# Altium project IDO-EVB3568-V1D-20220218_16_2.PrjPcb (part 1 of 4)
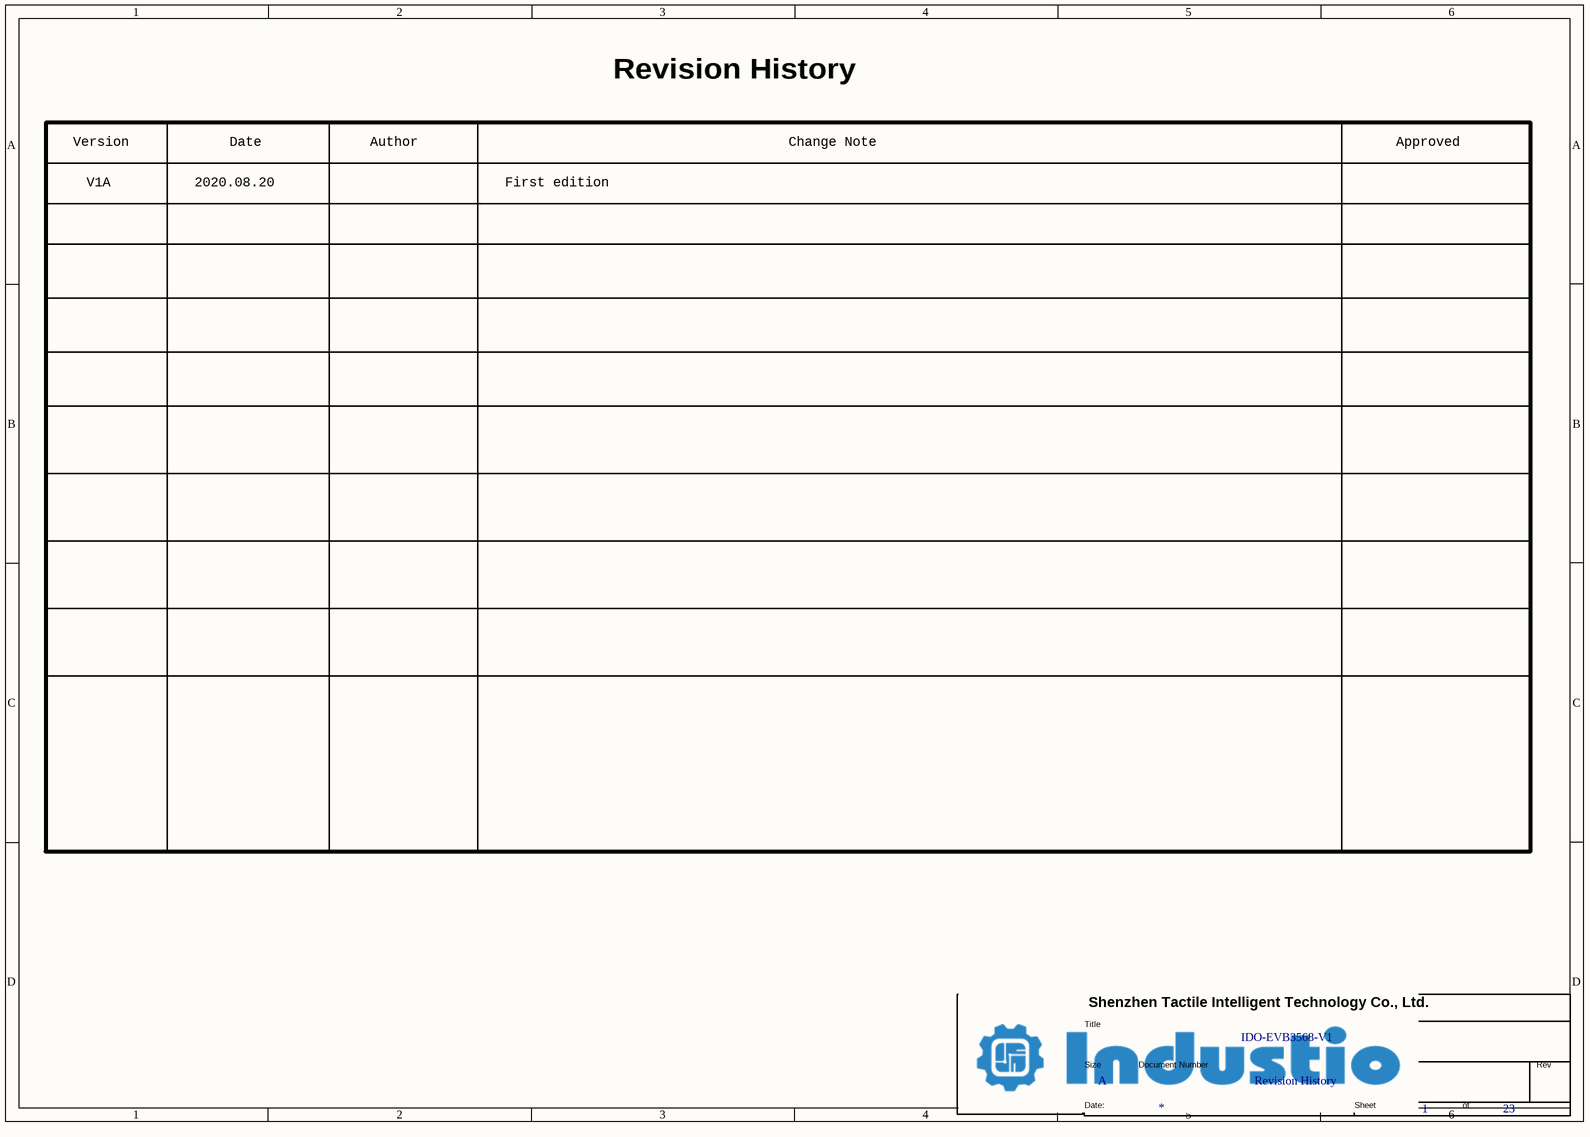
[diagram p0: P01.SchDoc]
23 sheets, 977 parts. Net scope: global (net labels, ports and power ports of the same name join across sheets).
Sheets:
  P01.SchDoc
  P02.SchDoc
  P03.SchDoc
  P04.SchDoc
  P05.SchDoc
  P06.SchDoc
  P07.SchDoc
  P08.SchDoc
  P09.SchDoc
  P10.SchDoc
  P11.SchDoc
  P12.SchDoc
  P13.SchDoc
  P14.SchDoc
  P15.SchDoc
  P16.SchDoc
  P17.SchDoc
  P18.SchDoc
  P19.SchDoc
  P20.SchDoc
  P21.SchDoc
  P22.SchDoc
  P23.SchDoc

## Sheet P01.SchDoc
size 297 x 209 mm

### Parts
(Parts that share a designator on the sheet are numbered #1, #2 ... from top to bottom, then left to right.)
*#1  Doc: Revision History  Title: IDO-EVB3568-V1  Page Size: A  Page Number: 1  Page Count: 23  (hidden comment: TitleBlock1)  (graphical)

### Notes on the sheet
- Revision History
- Version
- V1A
- 2020.08.20
- Date
- Author
- First edition
- Change Note
- Approved

## Sheet P02.SchDoc
size 594 x 420 mm
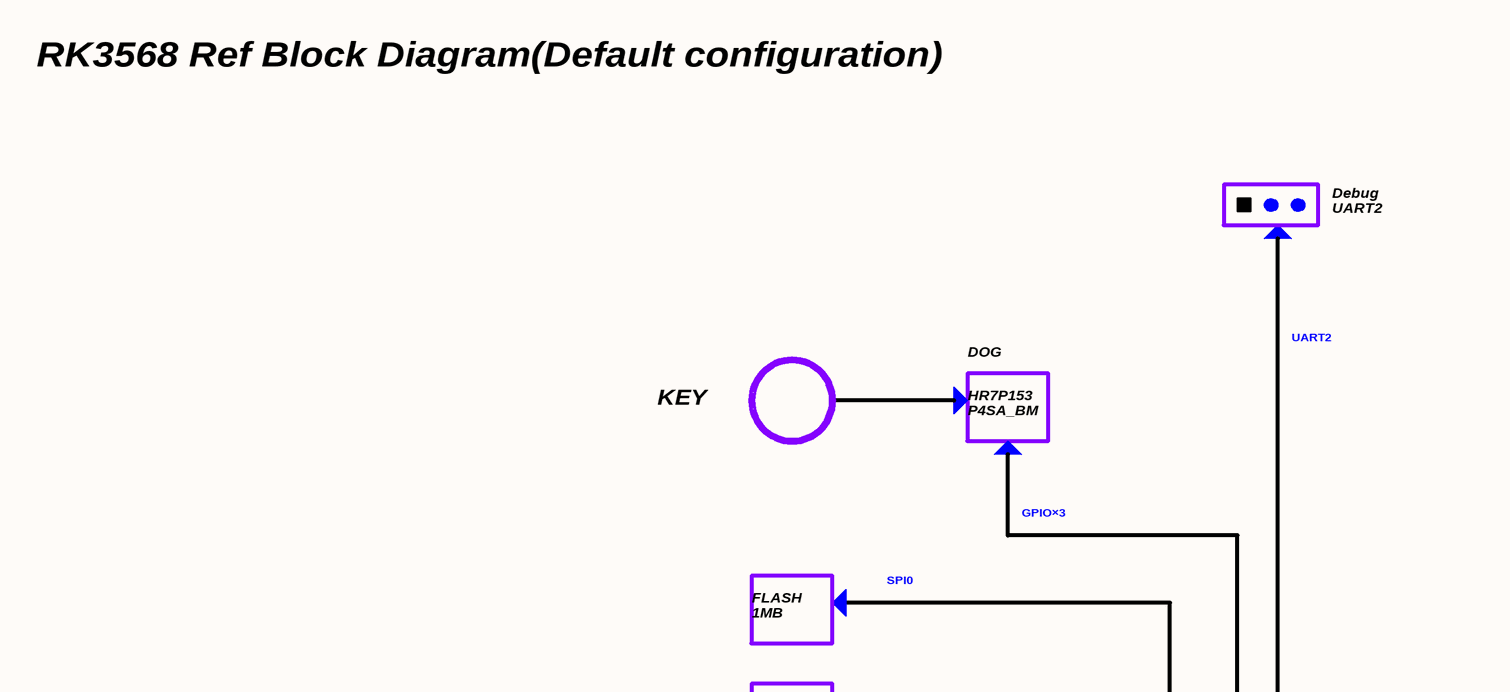
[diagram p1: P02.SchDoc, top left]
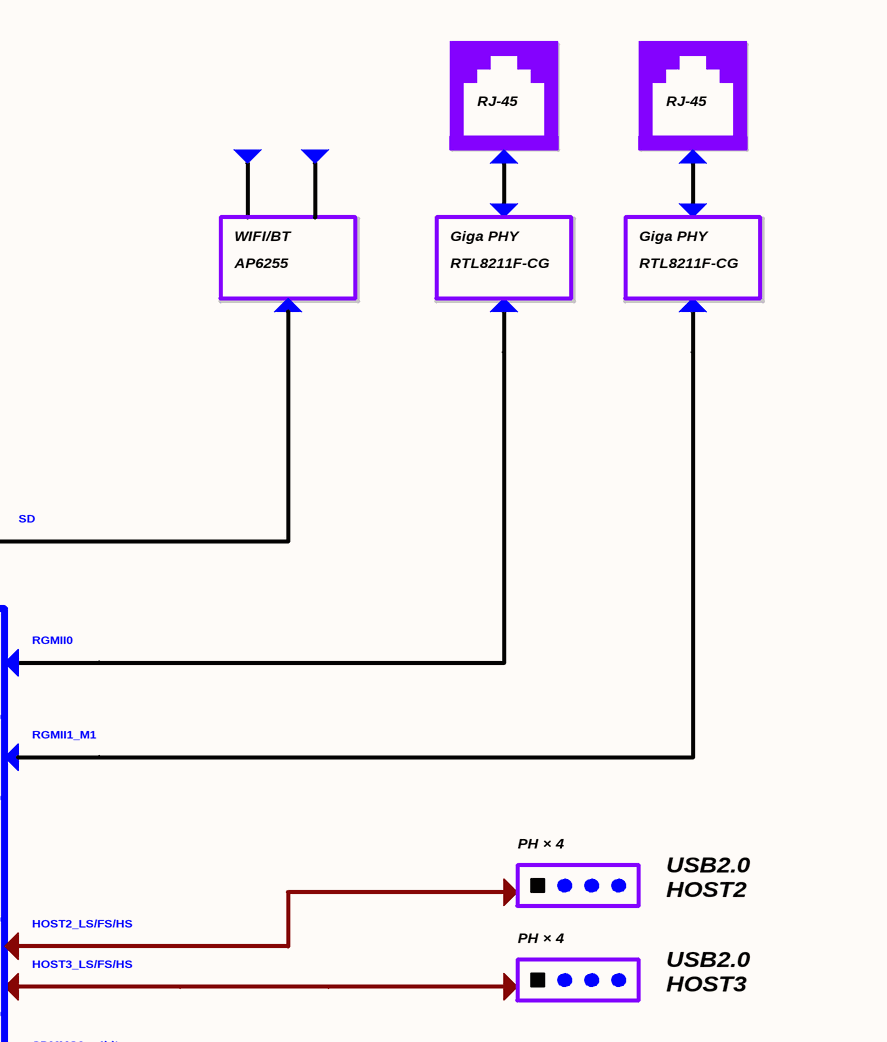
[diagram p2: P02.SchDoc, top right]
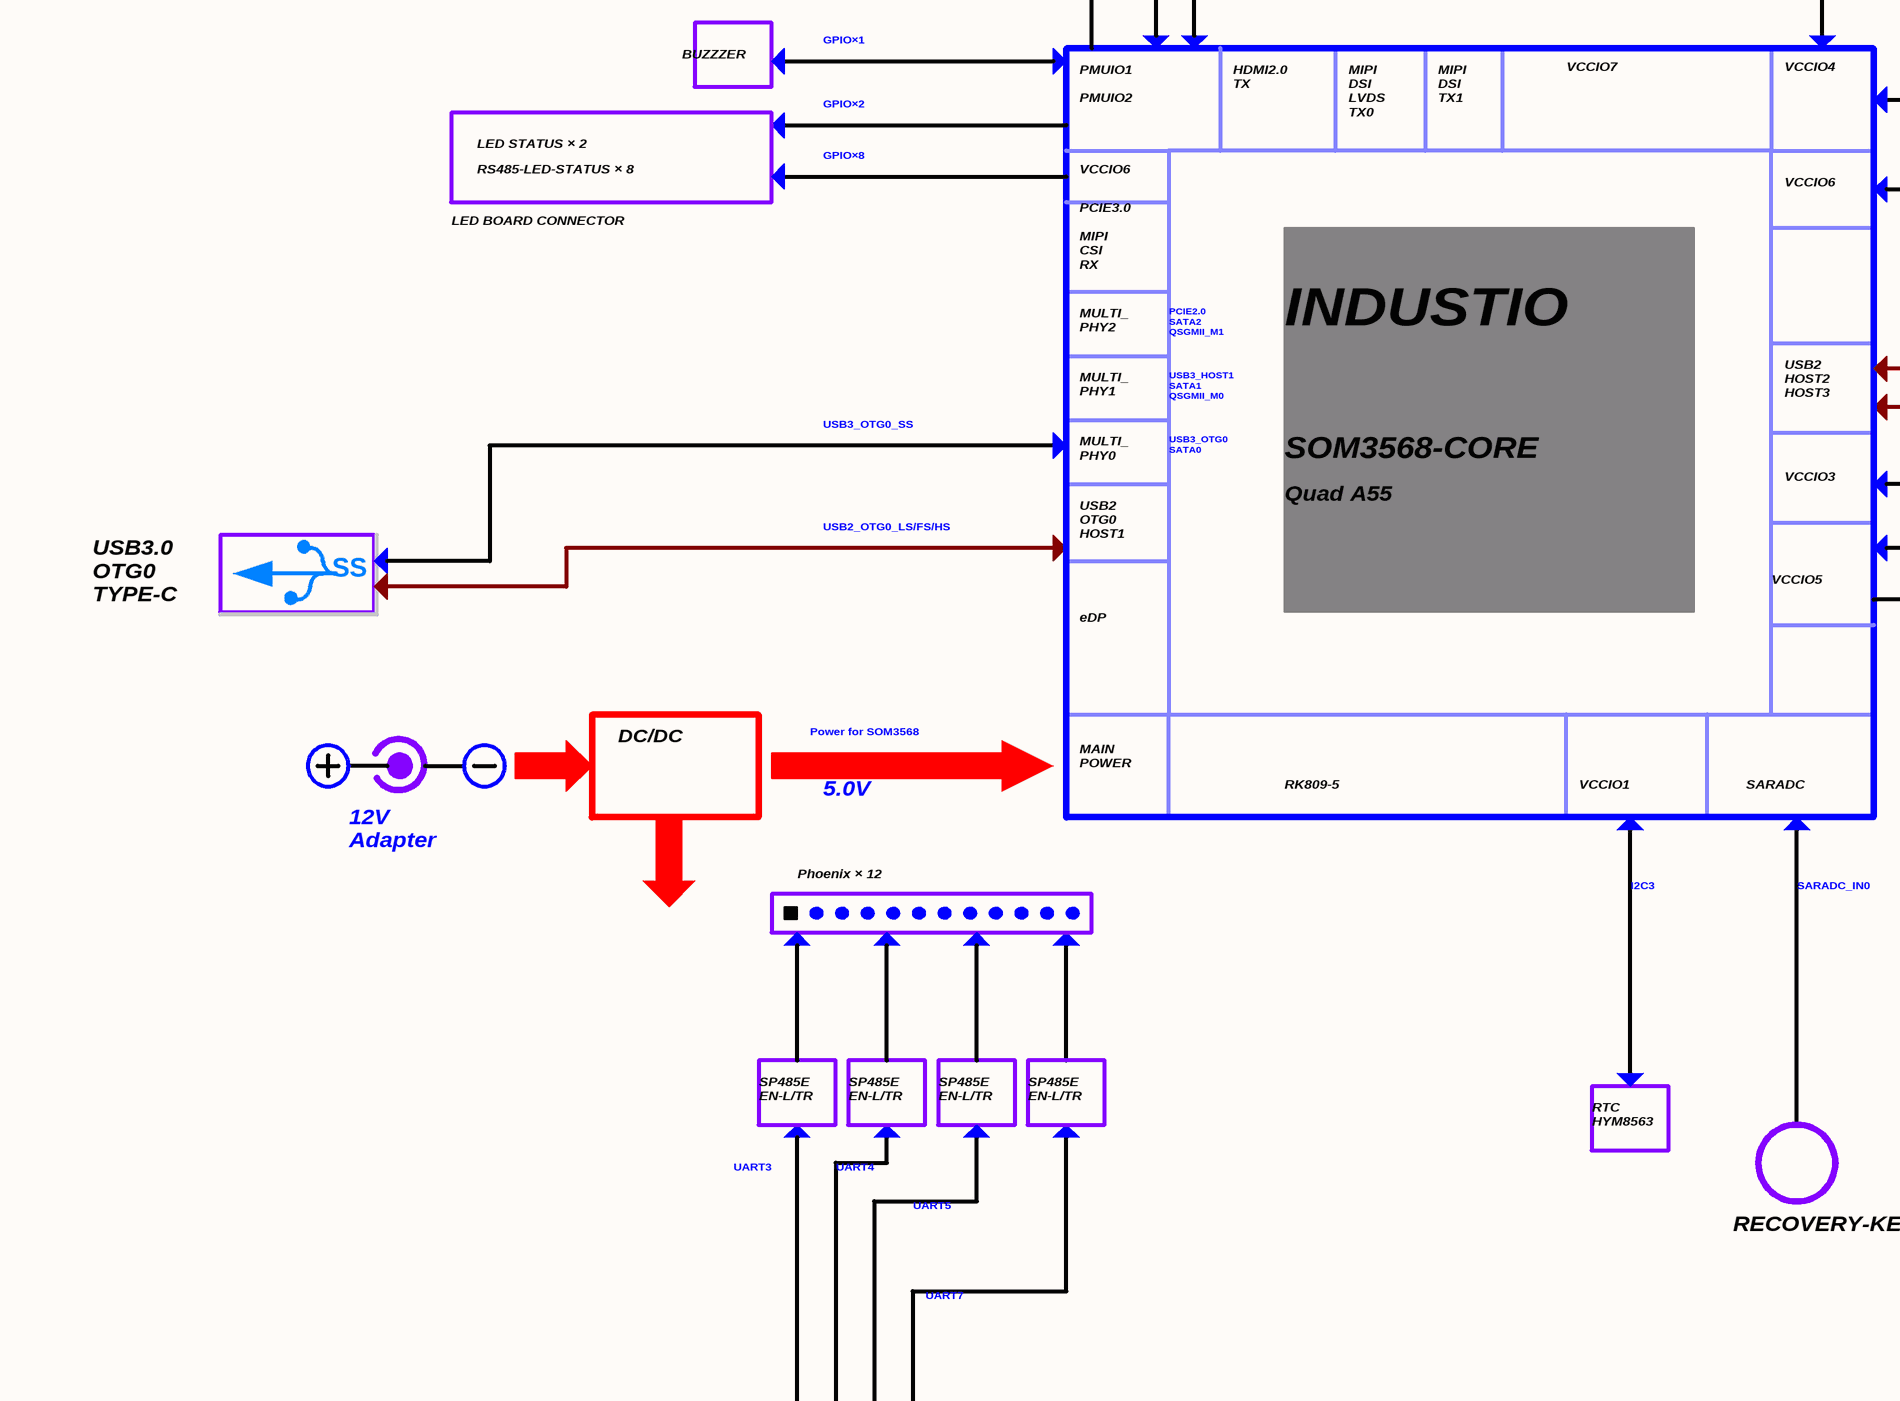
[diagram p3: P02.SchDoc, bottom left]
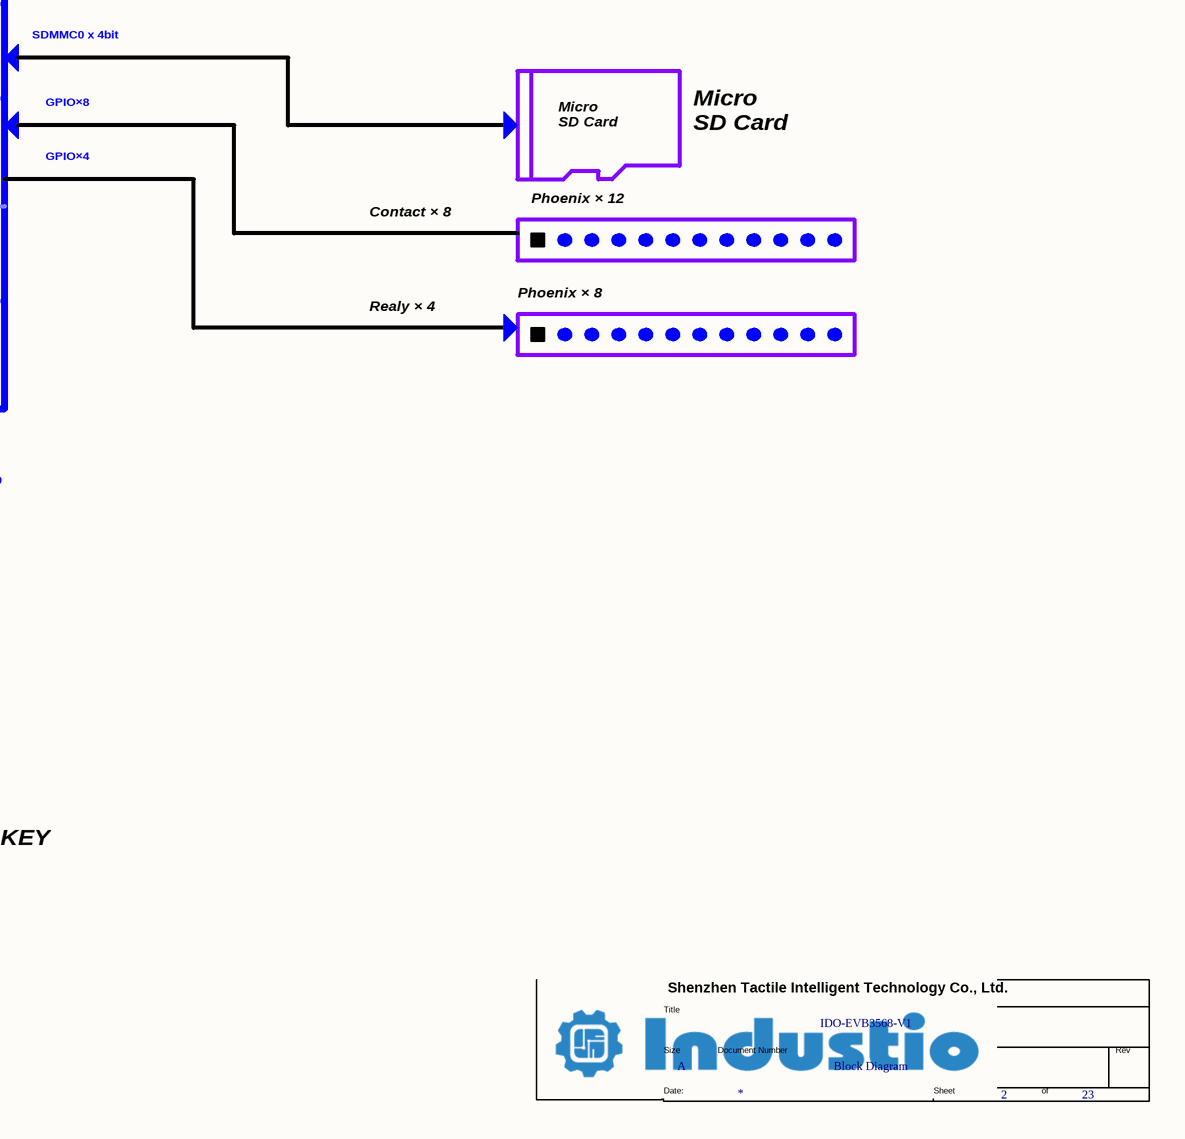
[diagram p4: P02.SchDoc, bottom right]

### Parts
(Parts that share a designator on the sheet are numbered #1, #2 ... from top to bottom, then left to right.)
*#2  Doc: Block Diagram  Title: IDO-EVB3568-V1  Page Size: A  Page Number: 2  Page Count: 23  (hidden comment: TitleBlock1)  (graphical)

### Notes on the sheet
- RK3568 Ref Block Diagram(Default configuration)
- Debug
  UART2
- RJ-45
- DOG
- UART2
- WIFI/BT
- Giga PHY
- KEY
- HR7P153
  P4SA_BM
- AP6255
- RTL8211F-CG
- GPIO×3
- FLASH
  1MB
- SPI0
- SD
- BUZZZER
- GPIO×1
- PMUIO1
  PMUIO2
- HDMI2.0
  TX
- MIPI
  DSI
  LVDS
  TX0
- MIPI
  DSI
  TX1
- VCCIO7
- VCCIO4
- RGMII0
- LED STATUS × 2
- GPIO×2
- GPIO×8
- LED BOARD CONNECTOR
- RS485-LED-STATUS × 8
- PCIE3.0
- MIPI
  CSI
  RX
- VCCIO6
- RGMII1_M1
- PH × 4
- USB2.0
  HOST2
- MULTI_
  PHY2
- PCIE2.0
  SATA2
  QSGMII_M1
- INDUSTIO
- USB2
  HOST2
  HOST3
- HOST2_LS/FS/HS
- MULTI_
  PHY1
- USB3_HOST1
  SATA1
  QSGMII_M0
- HOST3_LS/FS/HS
- USB2.0
  HOST3
- USB3_OTG0_SS
- MULTI_
  PHY0
- USB3_OTG0
  SATA0
- SOM3568-CORE
- VCCIO3
- SDMMC0 x 4bit
- USB3.0
  OTG0
  TYPE-C
- USB2_OTG0_LS/FS/HS
- USB2
  OTG0
  HOST1
- Quad A55
- Micro
  SD Card
- SS
- VCCIO5
- GPIO×4
- eDP
- Contact × 8
- Phoenix × 12
- Power for SOM3568
- MAIN
  POWER
- Realy × 4
- Phoenix × 8
- 12V
  Adapter
- DC/DC
- 5.0V
- RK809-5
- VCCIO1
- SARADC
- I2C3
- SARADC_IN0
- SP485E
  EN-L/TR
- RTC
  HYM8563
- UART3
- UART4
- UART5
- RECOVERY-KEY
- UART7

## Sheet P03.SchDoc
size 594 x 420 mm
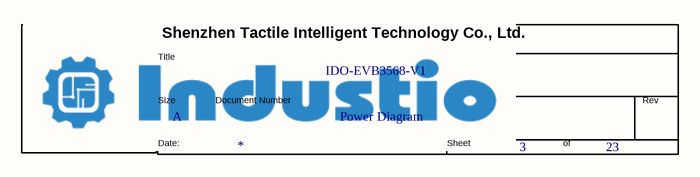
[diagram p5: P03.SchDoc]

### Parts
(Parts that share a designator on the sheet are numbered #1, #2 ... from top to bottom, then left to right.)
*#3  Doc: Power Diagram  Title: IDO-EVB3568-V1  Page Size: A  Page Number: 3  Page Count: 23  (hidden comment: TitleBlock1)  (graphical)

## Sheet P04.SchDoc
size 420 x 297 mm
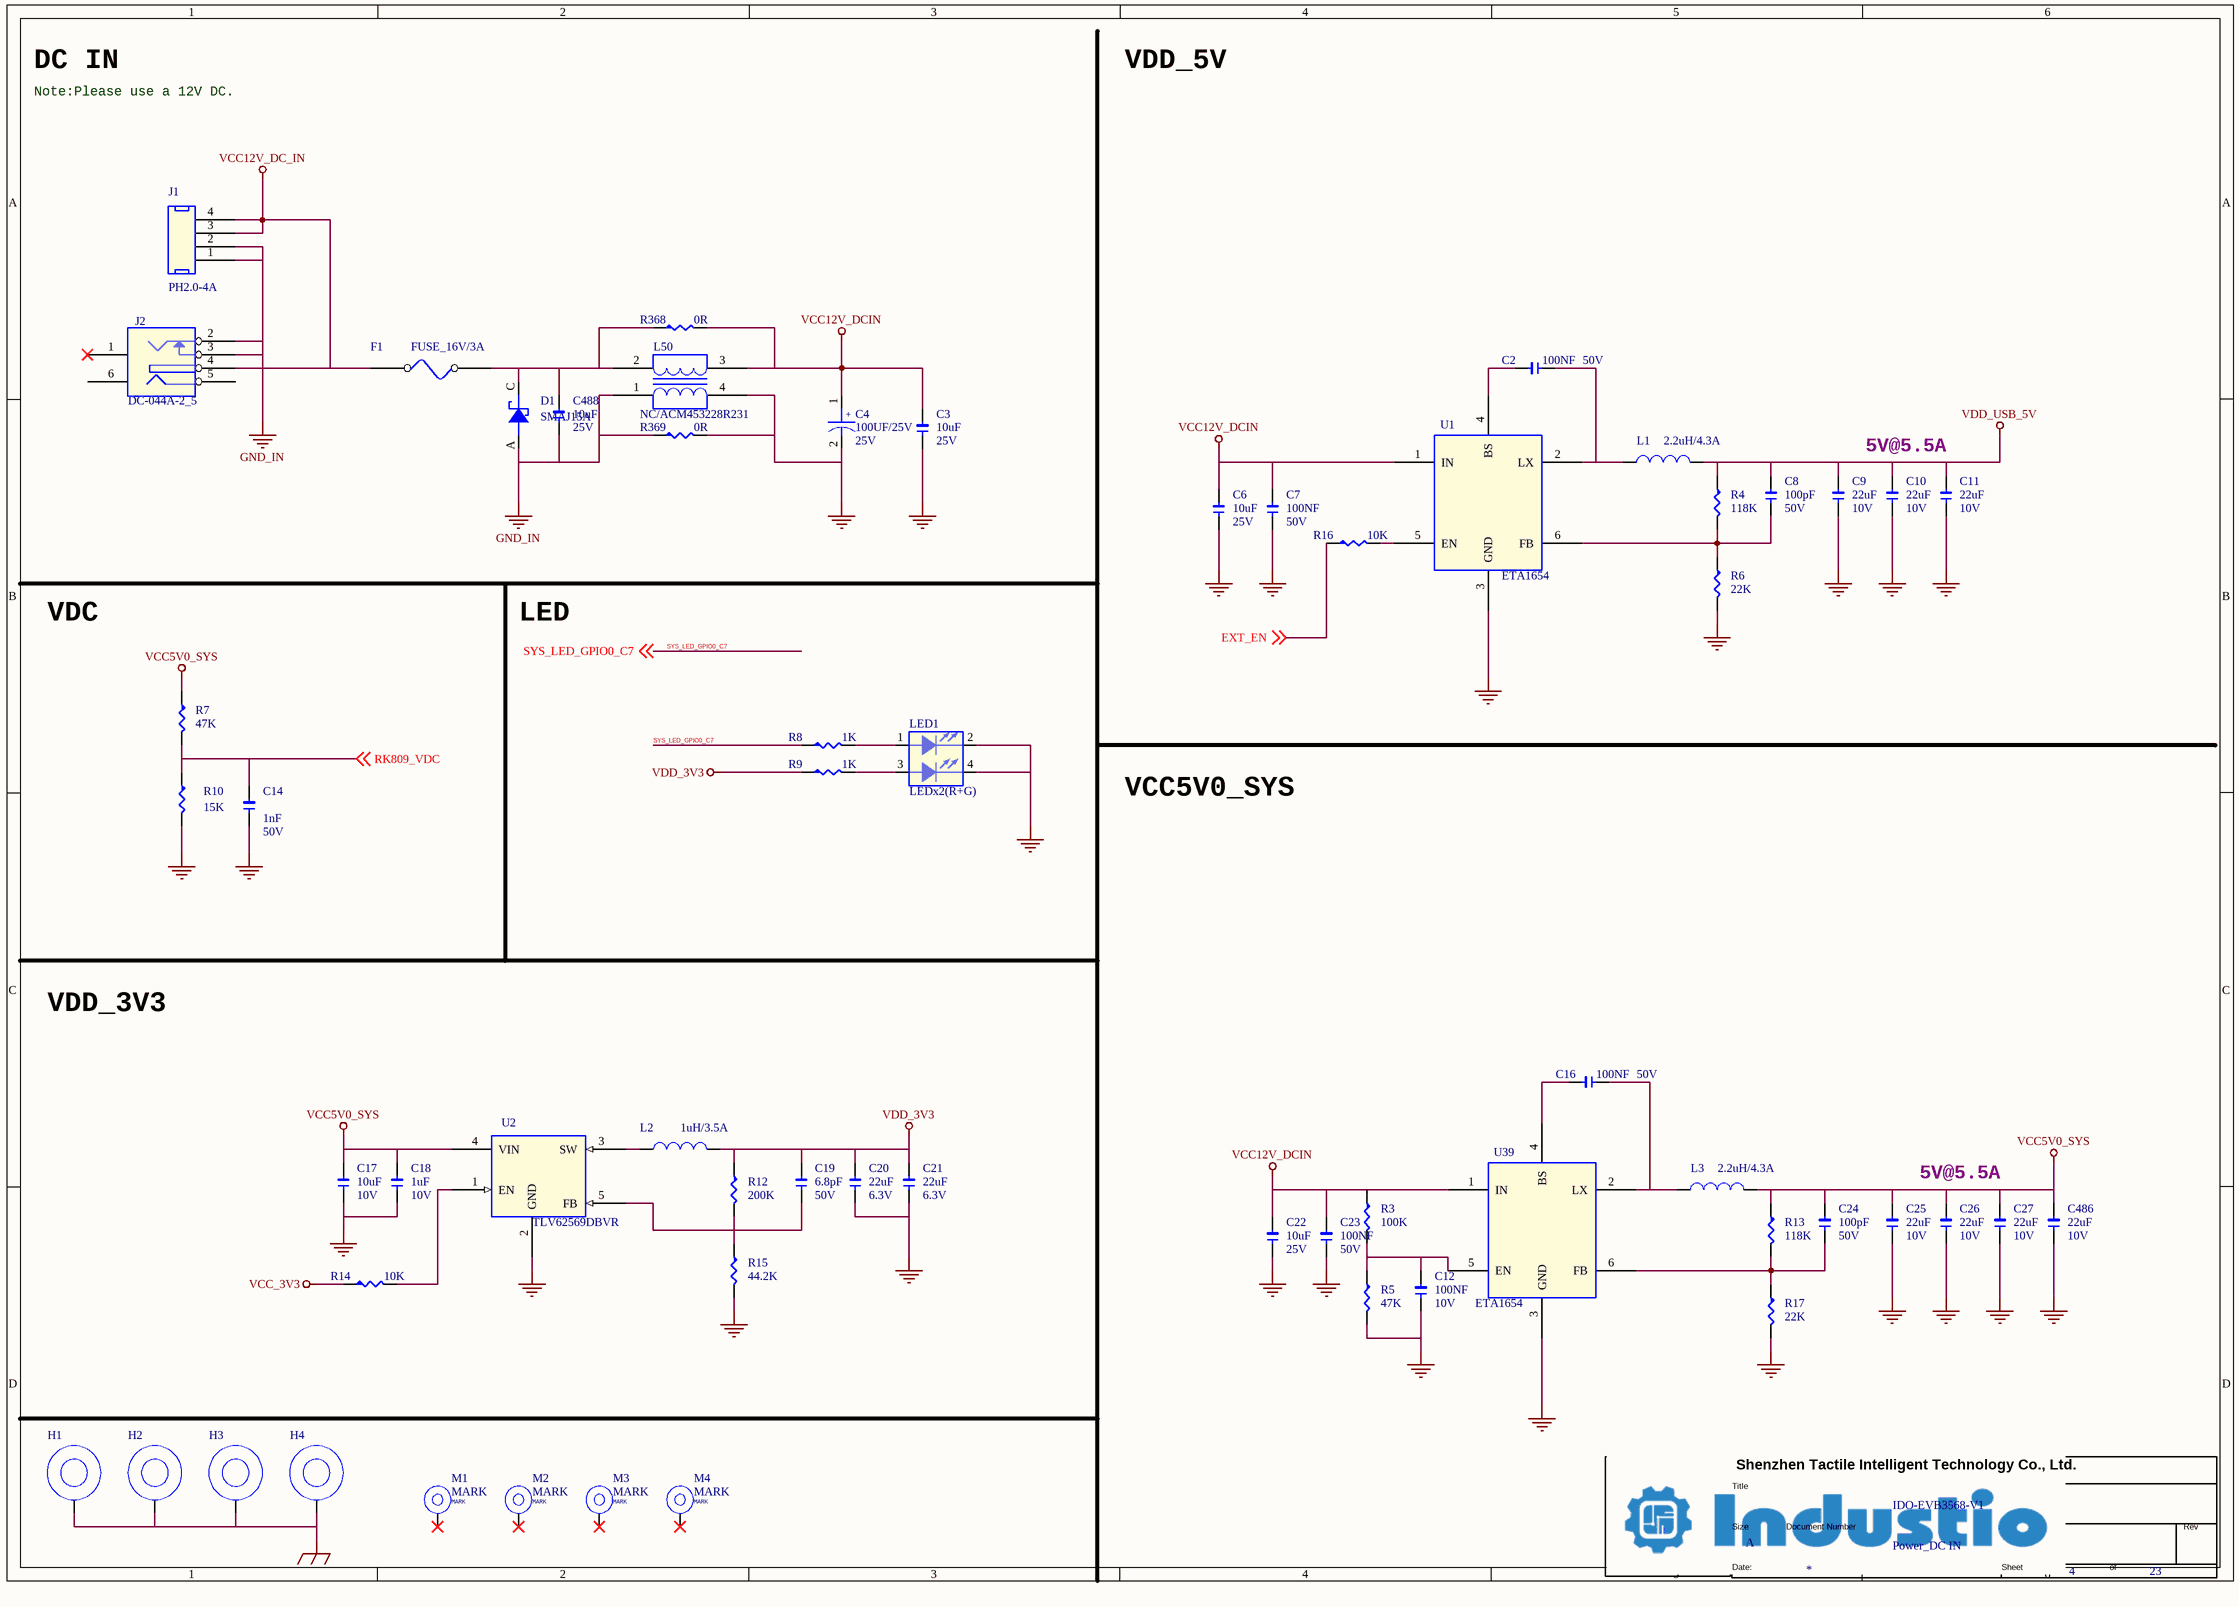
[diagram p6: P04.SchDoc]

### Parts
(Parts that share a designator on the sheet are numbered #1, #2 ... from top to bottom, then left to right.)
*#4  Doc: Power_DC IN  Title: IDO-EVB3568-V1  Page Size: A  Page Number: 4  Page Count: 23  (hidden comment: TitleBlock1)  (graphical)
C2  100NF  DSC2: 50V  [1206]
C3  10uF  DSC2: 25V  [1206]
C4  100UF/25V  DSC2: 25V  [CAPAE660X770]
C6  10uF  DSC2: 25V  [1206]
C7  100NF  DSC2: 50V  [1206]
C8  100pF  DSC2: 50V  [1206]
C9  22uF  DSC2: 10V  [1206]
C10  22uF  DSC2: 10V  [1206]
C11  22uF  DSC2: 10V  [1206]
C12  100NF  DSC2: 10V  [1206]
C14  1nF  DSC2: 50V  [1206]
C16  100NF  DSC2: 50V  [1206]
C17  10uF  DSC2: 10V  [1206]
C18  1uF  DSC2: 10V  [1206]
C19  6.8pF  DSC2: 50V  [1206]
C20  22uF  DSC2: 6.3V  [1206]
C21  22uF  DSC2: 6.3V  [1206]
C22  10uF  DSC2: 25V  [1206]
C23  100NF  DSC2: 50V  [1206]
C24  100pF  DSC2: 50V  [1206]
C25  22uF  DSC2: 10V  [1206]
C26  22uF  DSC2: 10V  [1206]
C27  22uF  DSC2: 10V  [1206]
C486  22uF  DSC2: 10V  [1206]
C488  10uF  DSC2: 25V  [1206]
D1  SMAJ15A  [SMA_DO-214AC]
F1  FUSE_16V/3A  [SMD1812]
H1  Hole  [mtg300_500]  (value not drawn)
H2  Hole  [mtg300_500]  (value not drawn)
H3  Hole  [mtg300_500]  (value not drawn)
H4  Hole  [mtg300_500]  (value not drawn)
J1  PH2.0-4A  [PH200-4A]
J2  DC-044A-2_5  [DC-044A-2_5]
L1  2.2uH/4.3A  [L4040]
L2  1uH/3.5A  [L2520]
L3  2.2uH/4.3A  [L4040]
L50  NC/ACM453228R231  [CMLP-ACM4532]
LED1  LEDx2(R+G)  [LED_P254_2X2DIP]
M1  MARK  [MARK]
M2  MARK  [MARK]
M3  MARK  [MARK]
M4  MARK  [MARK]
R3  100K  [R0402L]
R4  118K  [R0402L]
R5  47K  [R0402L]
R6  22K  [R0402L]
R7  47K  [R0402L]
R8  1K  [R0402L]
R9  1K  [R0402L]
R10  15K  [R0402L]
R12  200K  [R0402L]
R13  118K  [R0402L]
R14  10K  [R0402L]
R15  44.2K  [R0402L]
R16  10K  [R0402L]
R17  22K  [R0402L]
R368  0R  [R0805L]
R369  0R  [R0805L]
U1  ETA1654  [SOT563]
U2  TLV62569DBVR  [SOT23-5]
U39  ETA1654  [SOT563]

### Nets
GND: C3.1 C4.2 C6.1 C7.1 C9.1 C10.1 C11.1 C12.1 C14.1 C17.1 C18.1 C20.1 C21.1 C22.1 C23.1 C25.1 C26.1 C27.1 C486.1 L50.4 LED1.2 LED1.4 R5.2 R6.2 R10.2 R15.2 R17.2 R369.2 U1.3(GND) U2.2(GND) U39.3(GND)
GND_EARTH: H1.1 H2.1 H3.1 H4.1
GND_IN: C488.1 D1.A J1.1 J1.2 J2.2 J2.3 L50.1 R369.1
VCC5V0_SYS: C17.2 C18.2 C24.2 C25.2 C26.2 C27.2 C486.2 L3.2 R7.1 R13.1 U2.4(VIN)
VCC12V_DC_IN: F1.1 J1.3 J1.4 J2.4
VCC12V_DCIN: C3.2 C4.1 C6.2 C7.2 C22.2 C23.2 L50.3 R3.1 R368.2 U1.1(IN) U39.1(IN)
VCC_3V3: R14.1
VDD_3V3: C19.2 C20.2 C21.2 L2.2 R9.1 R12.1
VDD_USB_5V: C8.2 C9.2 C10.2 C11.2 L1.2 R4.1
EXT_EN: R16.1 ; off-sheet EXT_EN
RK809_VDC: C14.2 R7.2 R10.1 ; off-sheet RK809_VDC
SYS_LED_GPIO0_C7: R8.1 ; off-sheet SYS_LED_GPIO0_C7  [project net HDMITX_CEC_M1/PWM0_M1/UART0_CTSn/GPIO0_C7_d]
NetC2_1: C2.1 L1.1 U1.2(LX)
NetC2_2: C2.2 U1.4(BS)
NetC8_1: C8.1 R4.2 R6.1 U1.6(FB)
NetC12_2: C12.2 R3.2 R5.1 U39.5(EN)
NetC16_1: C16.1 L3.1 U39.2(LX)
NetC16_2: C16.2 U39.4(BS)
NetC19_1: C19.1 R12.2 R15.1 U2.5(FB)
NetC24_1: C24.1 R13.2 R17.1 U39.6(FB)
NetC488_2: C488.2 D1.C F1.2 L50.2 R368.1
NetL2_1: L2.1 U2.3(SW)
NetLED1_1: LED1.1 R8.2
NetLED1_3: LED1.3 R9.2
NetR14_2: R14.2 U2.1(EN)
NetR16_2: R16.2 U1.5(EN)

Not connected (* = marked no-connect by the designer): J2 1* 5 6; M1 1*; M2 1*; M3 1*; M4 1*

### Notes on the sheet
- DC IN
- Note:Please use a 12V DC.
- VDD_5V
- 5V@5.5A
- VDC
- LED
- VCC5V0_SYS
- VDD_3V3

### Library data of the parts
C2 C7 = C-0402_Dup1: Manufacture: 三星¦国巨¦村田; Part Name: 贴片电容; Part Number: C020102120061; ID: 61; DSC3: X7R; DSC1: ±10%; ERP Number: 1010200128; PCB Footprint: C0402L
C3 C6 C488 = C-0805: Part Number: C020102120074; Part Name: 贴片电容; Manufacture: 三星¦国巨¦村田; PCB Footprint: C0805L; ERP Number: 1010200144; DSC1: ±10%; DSC3: X5R; ID: 74
C4 = C-AL-SMD: Part Number: C020302140006; Part Name: 贴片铝电容; Manufacture: 先科¦立隆¦三莹; ERP Number: 1010200266; DSC1: ±20%; DSC3: 低阻抗; DSC4: 2000H; DSC5: -55~105 ℃; DSC6: SMD,6.3x7.7mm; DSC7: LZ1E101M-CRE77(ST); ID: 6
C8 C24 = C-0402: Part Number: C020102120040; Part Name: 贴片电容; Manufacture: 三星¦国巨¦村田; ERP Number: 1010200152; DSC1: ±5%; DSC3: C0G; PCB Footprint: C0402L
C9-C11 C25-C27 C486 = C-0805: Manufacture: 三星¦国巨¦村田; Part Name: 贴片电容; Part Number: C020102120075; PCB Footprint: C0805L; ID: 75; DSC3: X5R; DSC1: ±20%
C12 = C-0402_Dup1: Part Number: C020102120060; Part Name: 贴片电容; Manufacture: 三星¦国巨¦村田; PCB Footprint: C0402L; DSC1: ±10%; DSC3: X7R; ID: 60
C14 = C-0402_Dup1: Part Number: C020102120054; Part Name: 贴片电容; Manufacture: 三星¦国巨¦村田; PCB Footprint: C0402L; ERP Number: 1010200084; DSC1: ±10%; DSC3: X7R; ID: 54
C16 C23 = C-0402_Dup1: Part Number: C020102120061; Part Name: 贴片电容; Manufacture: 三星¦国巨¦村田; ERP Number: 1010200128; DSC1: ±10%; DSC3: X7R; ID: 61; PCB Footprint: C0402L
C17 = C-0603: Manufacture: 三星¦国巨¦村田; Part Name: 贴片电容; Part Number: C020102120071; ID: 71; DSC3: X5R; DSC1: ±20%; ERP Number: 1010200076; PCB Footprint: C0603L
C18 = C-0402_Dup1: Manufacture: 三星¦国巨¦村田; Part Name: 贴片电容; Part Number: C020102120064; ID: 64; DSC3: X5R; DSC1: ±10%; ERP Number: 1010200054; PCB Footprint: C0402L
C19 = C-0402_Dup1: Part Number: C020102120018; Part Name: 贴片电容; Manufacture: 三星¦国巨¦村田; ERP Number: 1010200056; DSC1: ±0.25PF; DSC3: C0G; ID: 18; PCB Footprint: C0402L
C20 = C-0603: Manufacture: 三星¦国巨¦村田; Part Name: 贴片电容; Part Number: C020102120072; ID: 72; DSC3: X5R; DSC1: ±20%; ERP Number: 1010200133; PCB Footprint: C0603L
C21 = C-0603: Part Number: C020102120072; Part Name: 贴片电容; Manufacture: 三星¦国巨¦村田; ERP Number: 1010200133; DSC1: ±20%; DSC3: X5R; ID: 72; PCB Footprint: C0603L
C22 = C-0805: Manufacture: 三星¦国巨¦村田; Part Name: 贴片电容; Part Number: C020102120074; PCB Footprint: C0805L; ID: 74; DSC3: X5R; DSC1: ±10%; ERP Number: 1010200144
D1 = DI-XI-S: Manufacture: MDD¦伯恩半导体; Part Name: TVS; Part Number: C040602260003; CLASS: IC; ID: 3; DSC6: Ppp=400W; DSC5: Ipp=16.4A; DSC4: Vc=24.4V; DSC3: VBR=16.7V; DSC2: Vrwm=15V; DSC1: 单向; ERP Number: 1010800027
F1 = FUSE-SMD1812: Part Number: C160102670008; Part Name: 自恢复保险丝; Manufacture: RUILON; DSC1: 16V; DSC2: 3A; DSC3: SMD1812P300TF/16V; ID: 8
J1 = J-H-4P: Part Number: J020302820003; Part Name: PH; DSC1: 4p; DSC2: 2.0mm间距; DSC3: 通孔180度直针; DSC4: 米黄色胶壳 耐高温; DSC5: A2001WV-4P(CJT); ID: 13
J2 = J-DC-044A-2_5: Part Name: DC座; Part Number: J100103010003; ID: 3; DSC4: DC-044A-2.5A-2.0(星坤); DSC3: 插件; DSC2: 11.5*10.1*H7.3mm; DSC1: DC电源 内芯2.0mm 外径6mm 5脚插件 有定位柱
L1 L3 = L-IND_Dup1: Part Name: 功率电感; Part Number: C060202340020; Manufacture: 顺络; ERP Number: 1010200404; DSC1: ±20%; DSC2: Isat=6.1A; DSC3: Irms=4.3A; DSC4: 48mΩ; DSC5: 4.0*4.0*2.0mm; DSC6: WPN4020H2R2MT(顺络); ID: 20
L2 = L-IND_Dup1: Manufacture: 顺络; Part Number: C060202340012; Part Name: 功率电感; ID: 12; DSC6: WPN252012E1R0MT(顺络); DSC5: 2.5*2.0*1.2mm; DSC4: 37mΩ; DSC3: Irms=3.5A; DSC2: Isat=4.5A; DSC1: ±20%
L50 = L-CMLS-ACM2012-1: Manufacture: 驰兴; Part Number: C060406183888; Part Name: 电源共模电感; DSC6: SMD_4P,4.5x3.2x2.8mm; DSC5: -40℃ ~ +85℃; DSC4: DCR=50mΩ; DSC3: 3.5A; DSC2: 231Ω@100MHz
LED1 = D-LED-DIP-2: Part Number: C140202660018; Part Name: LED; DSC1: 双孔座2位黑色方形灯柱 90度弯脚 左正右负 上红下绿; ID: 22
M1 = MARK: MARK Symble; Priority: A; RK PN: MARK01
M2-M4 = MARK: MARK Symble; RK PN: MARK01; Priority: A
R3 = R-0402_Dup1: Part Name: 贴片电阻; Part Number: C011002080976; ERP Number: 1010200137; DSC1: ±1%; DSC2: 1/16W; ID: 976
R4 = R-0402_Dup1: Part Name: 贴片电阻; Part Number: C011002080983; ERP Number: 1010200366; DSC1: ±1%; DSC2: 1/16W; ID: 983
R5 R7 = R-0402_Dup1: Part Number: C011002080935; Part Name: 贴片电阻; ID: 935; DSC2: 1/16W; DSC1: ±1%; ERP Number: 1010200446
R6 R17 = R-0402_Dup1: Part Name: 贴片电阻; Part Number: C011002080893; DSC1: ±1%; DSC2: 1/16W; ID: 893
R8 R9 = R-0402_Dup1: Part Number: C011002080742; Part Name: 贴片电阻; ID: 742; DSC2: 1/16W; DSC1: ±1%; ERP Number: 1010200113
R10 = R-0402_Dup1: Part Name: 贴片电阻; Part Number: C011002080875; ERP Number: 1010200458; DSC1: ±1%; DSC2: 1/16W; ID: 875
R12 = R-0402_Dup1: Part Number: C011002081009; Part Name: 贴片电阻; ID: 1,009; DSC2: 1/16W; DSC1: ±1%; ERP Number: 1010200139
R13 = R-0402_Dup1: Part Number: C011002080983; Part Name: 贴片电阻; ID: 983; DSC2: 1/16W; DSC1: ±1%; ERP Number: 1010200366
R14 R16 = R-0402_Dup1: Part Name: 贴片电阻; Part Number: C011002080856; ERP Number: 1010200140; DSC1: ±1%; DSC2: 1/16W; ID: 856
R15 = R-0402_Dup1: Part Number: C011002080931; Part Name: 贴片电阻; ID: 931; DSC2: 1/16W; DSC1: ±1%; ERP Number: 1010200256
R368 R369 = R-0805: Part Name: 贴片电阻; Part Number: C011002081448; ERP Number: 1010200199; DSC1: ±1%; DSC2: 1/8W; ID: 1,448
U1 = U-SY8105ADC_0: Part Name: DCDC; Part Number: C070202410017; Manufacture: 矽力杰; DSC1: Vi=4.5-18V; DSC2: Vo=0.6-18V; DSC3: Io=5A; DSC4: Vfb=0.6V; DSC5: 0.96; DSC6: 500KHz; DSC7: 同步降压
U2 = U-TLV62569DBVR: Part Name: DCDC; Part Number: C070202410003; Manufacture: TI; DSC1: Vi=2.5-5.5V; DSC2: Vo=0.6-5.5V; DSC3: Io=2A; DSC4: Vfb=0.6V; DSC5: 0.95; DSC6: 1.5MHz; DSC7: 同步降压 轻载效率 低Iq; Solder: 推荐; ID: 3
U39 = U-SY8105ADC_0: Manufacture: 矽力杰; Part Number: C070202410017; Part Name: DCDC; DSC7: 同步降压; DSC6: 500KHz; DSC5: 0.96; DSC4: Vfb=0.6V; DSC3: Io=5A; DSC2: Vo=0.6-18V; DSC1: Vi=4.5-18V

## Sheet P05.SchDoc
size 840 x 594 mm
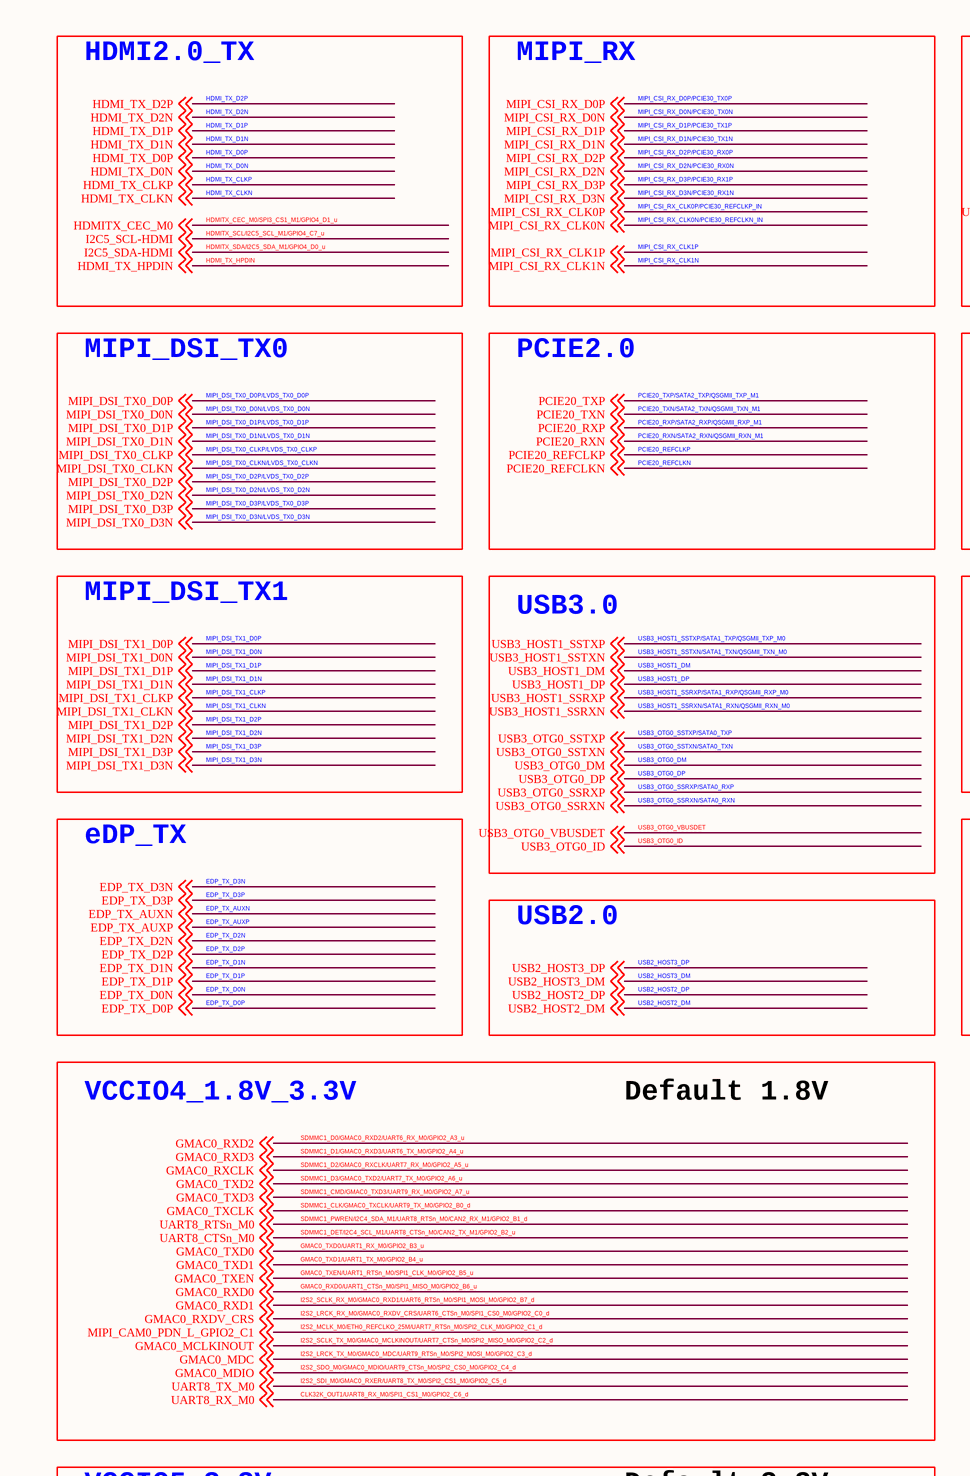
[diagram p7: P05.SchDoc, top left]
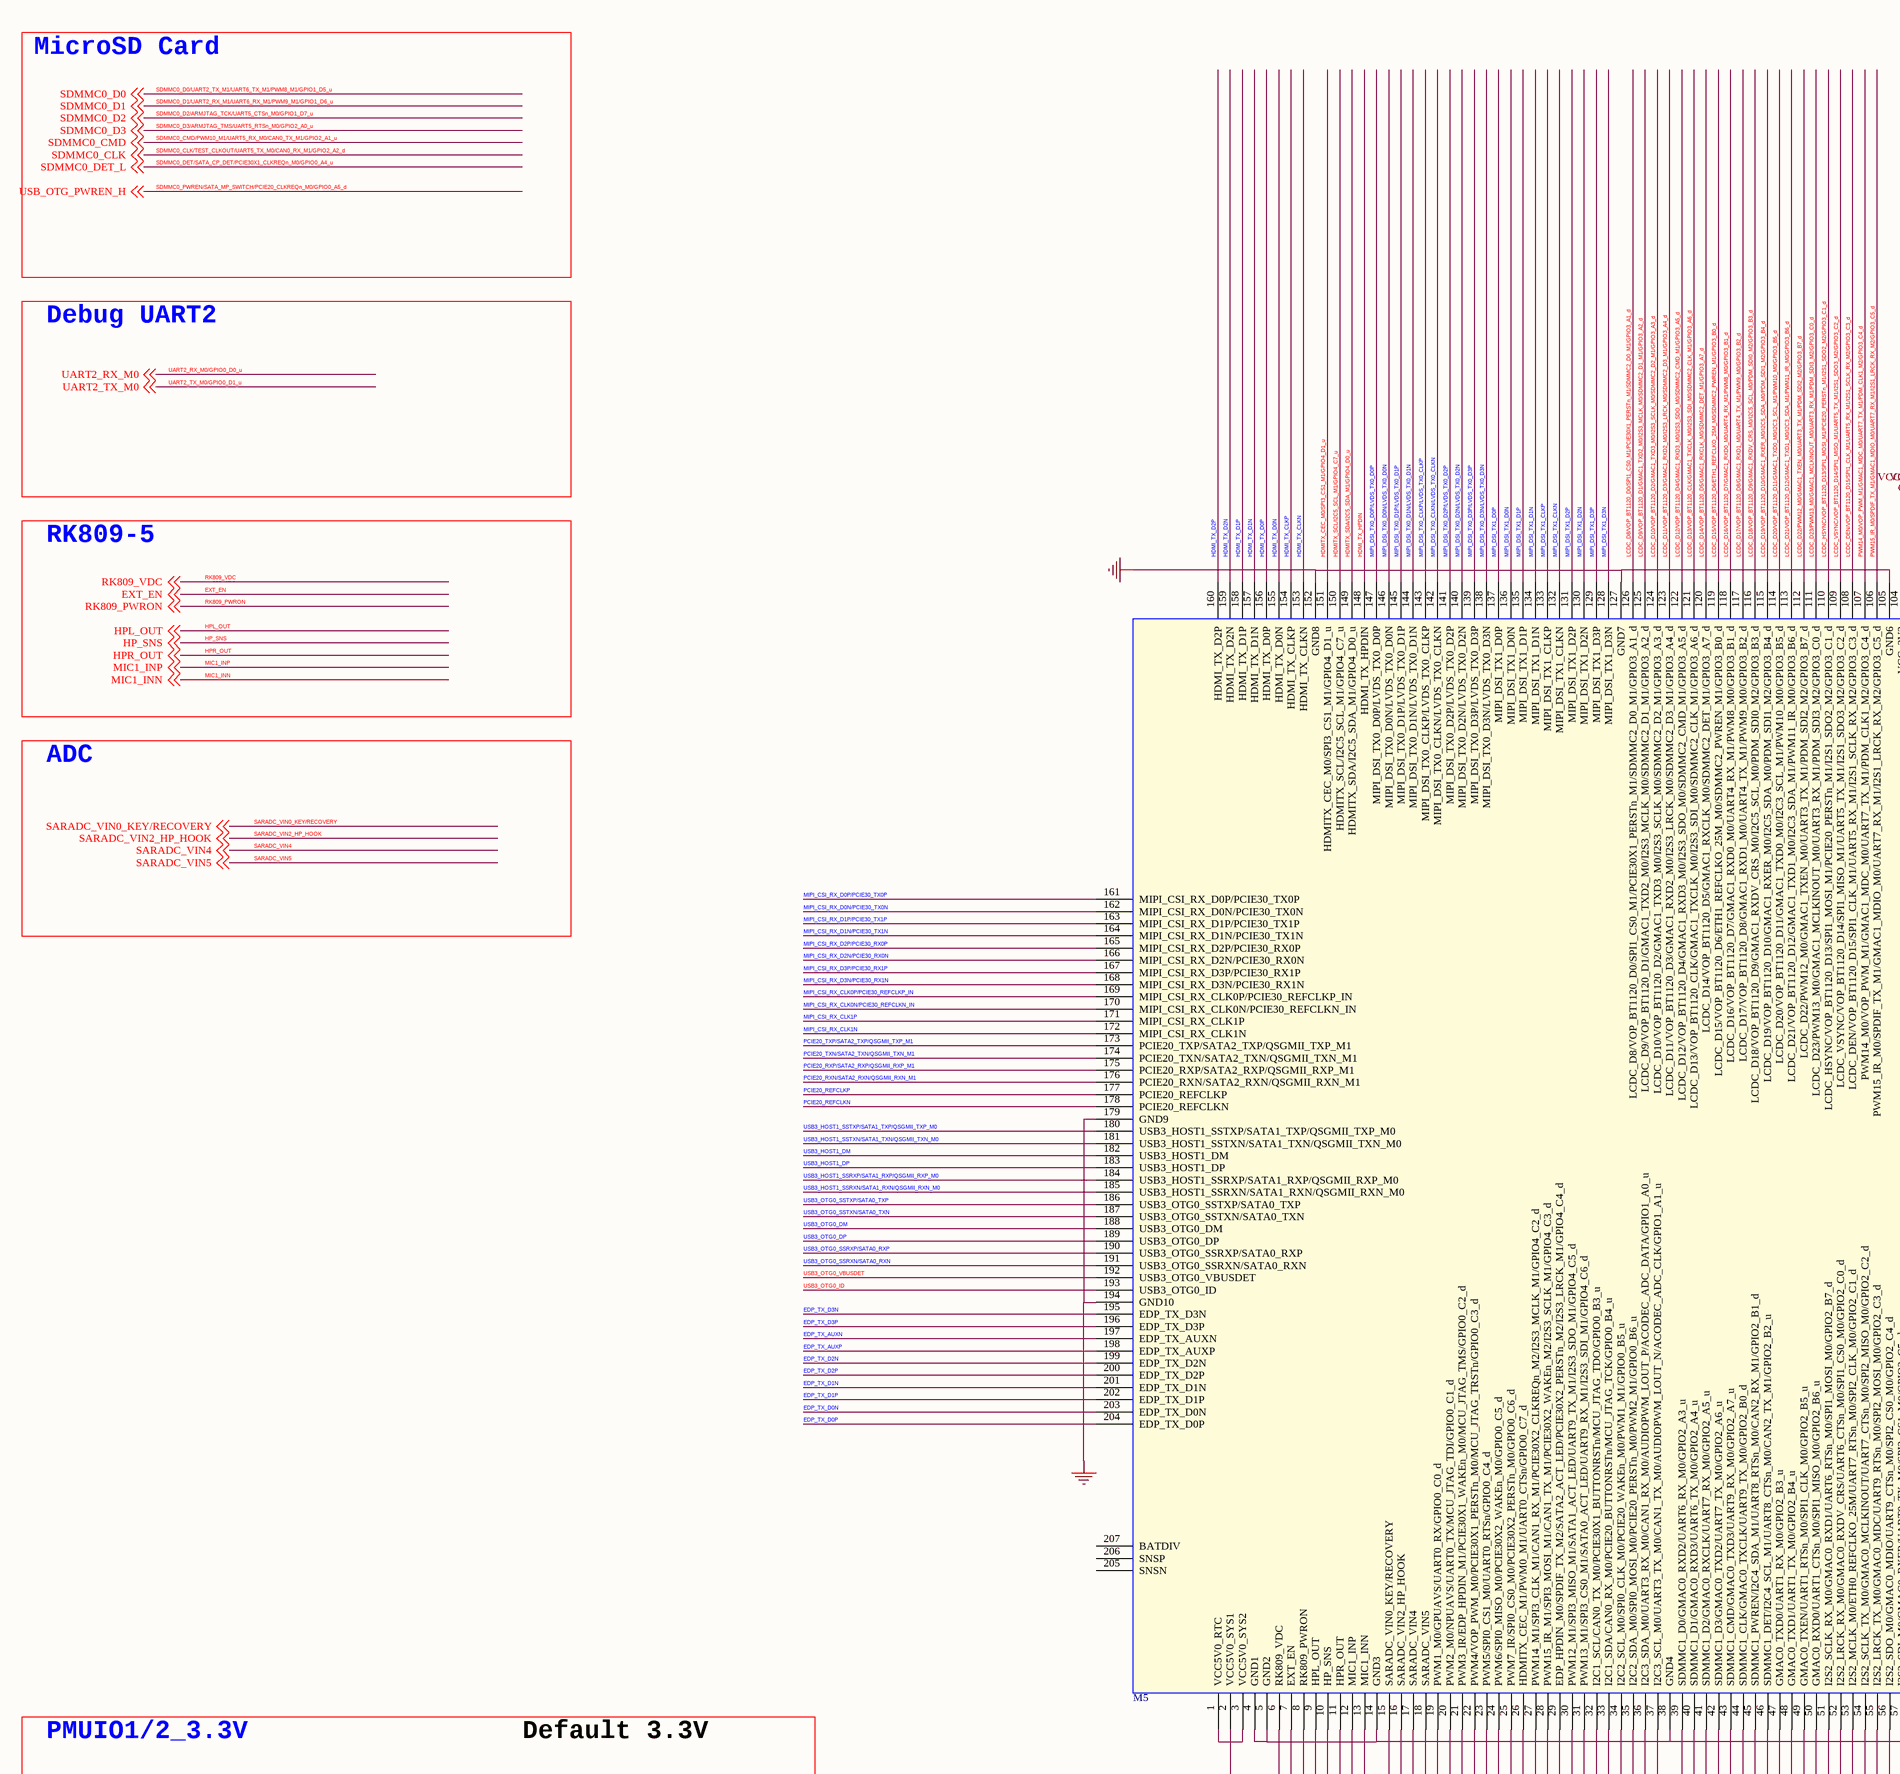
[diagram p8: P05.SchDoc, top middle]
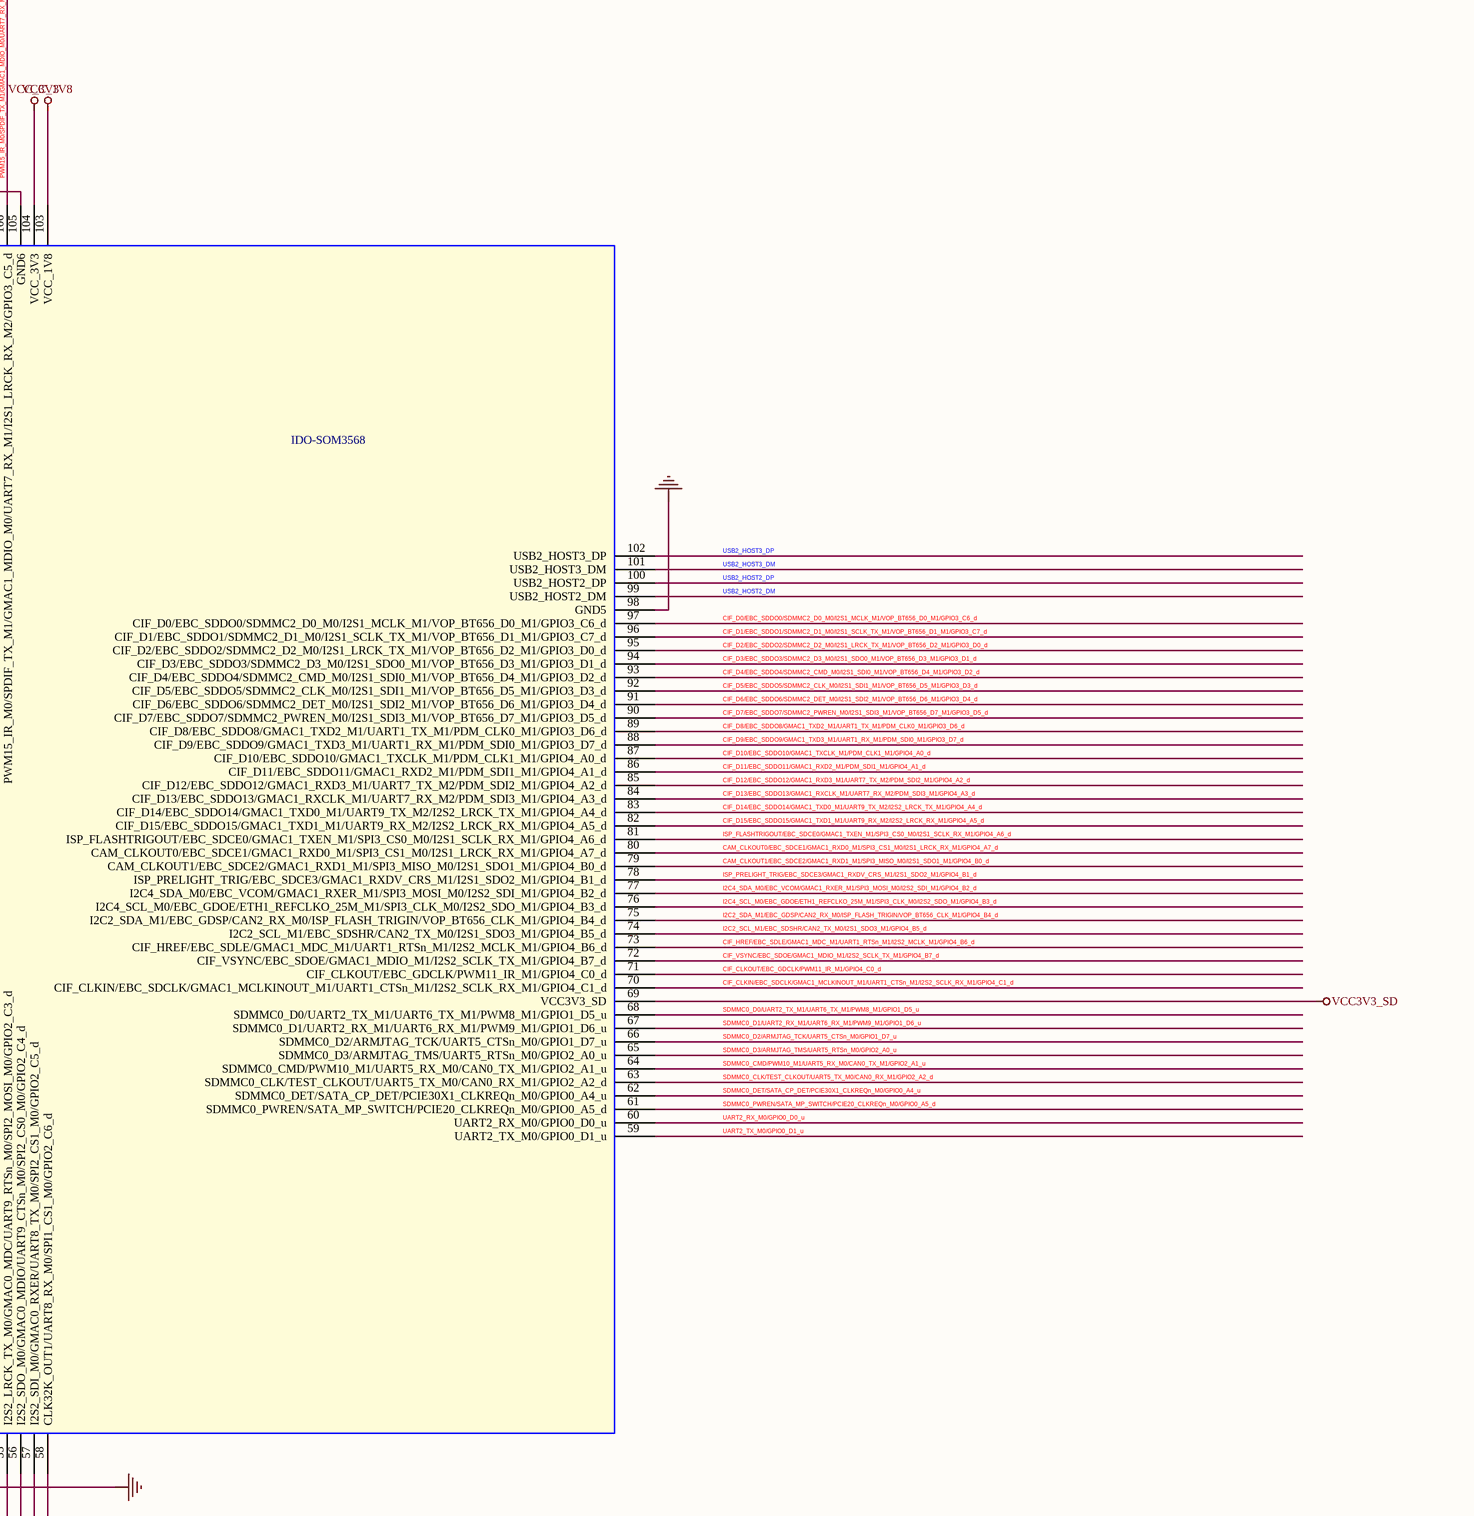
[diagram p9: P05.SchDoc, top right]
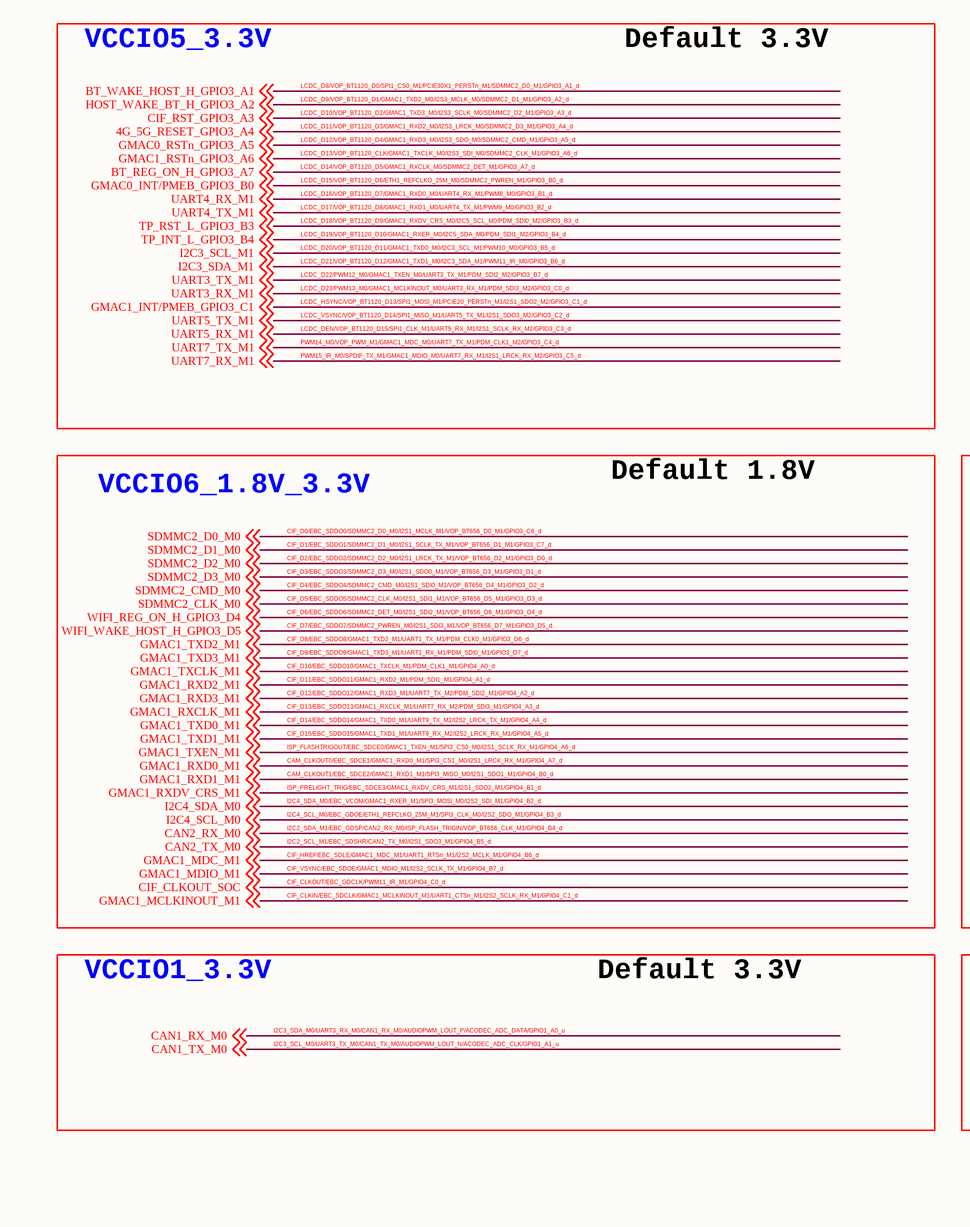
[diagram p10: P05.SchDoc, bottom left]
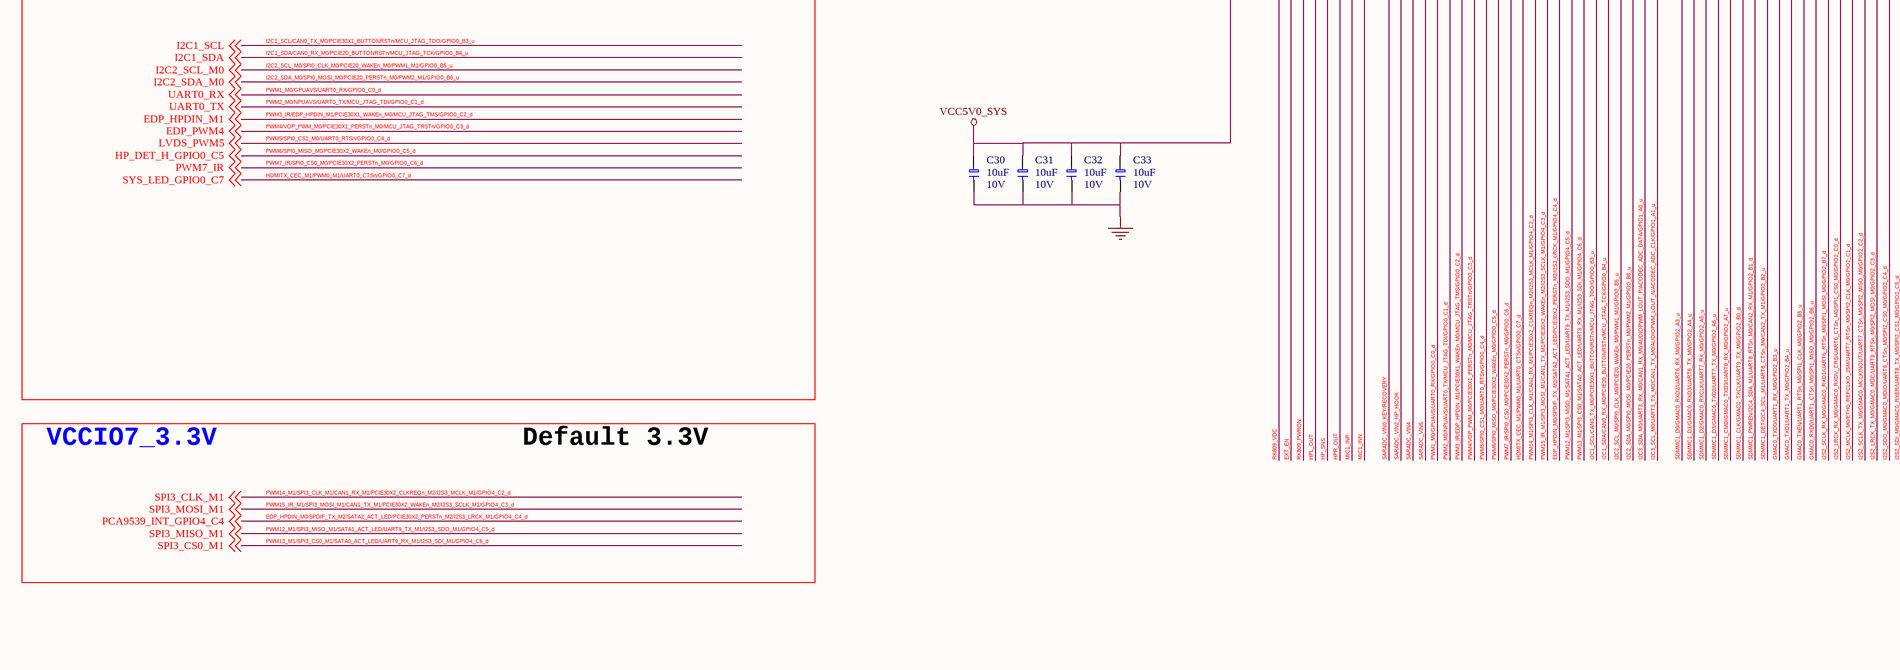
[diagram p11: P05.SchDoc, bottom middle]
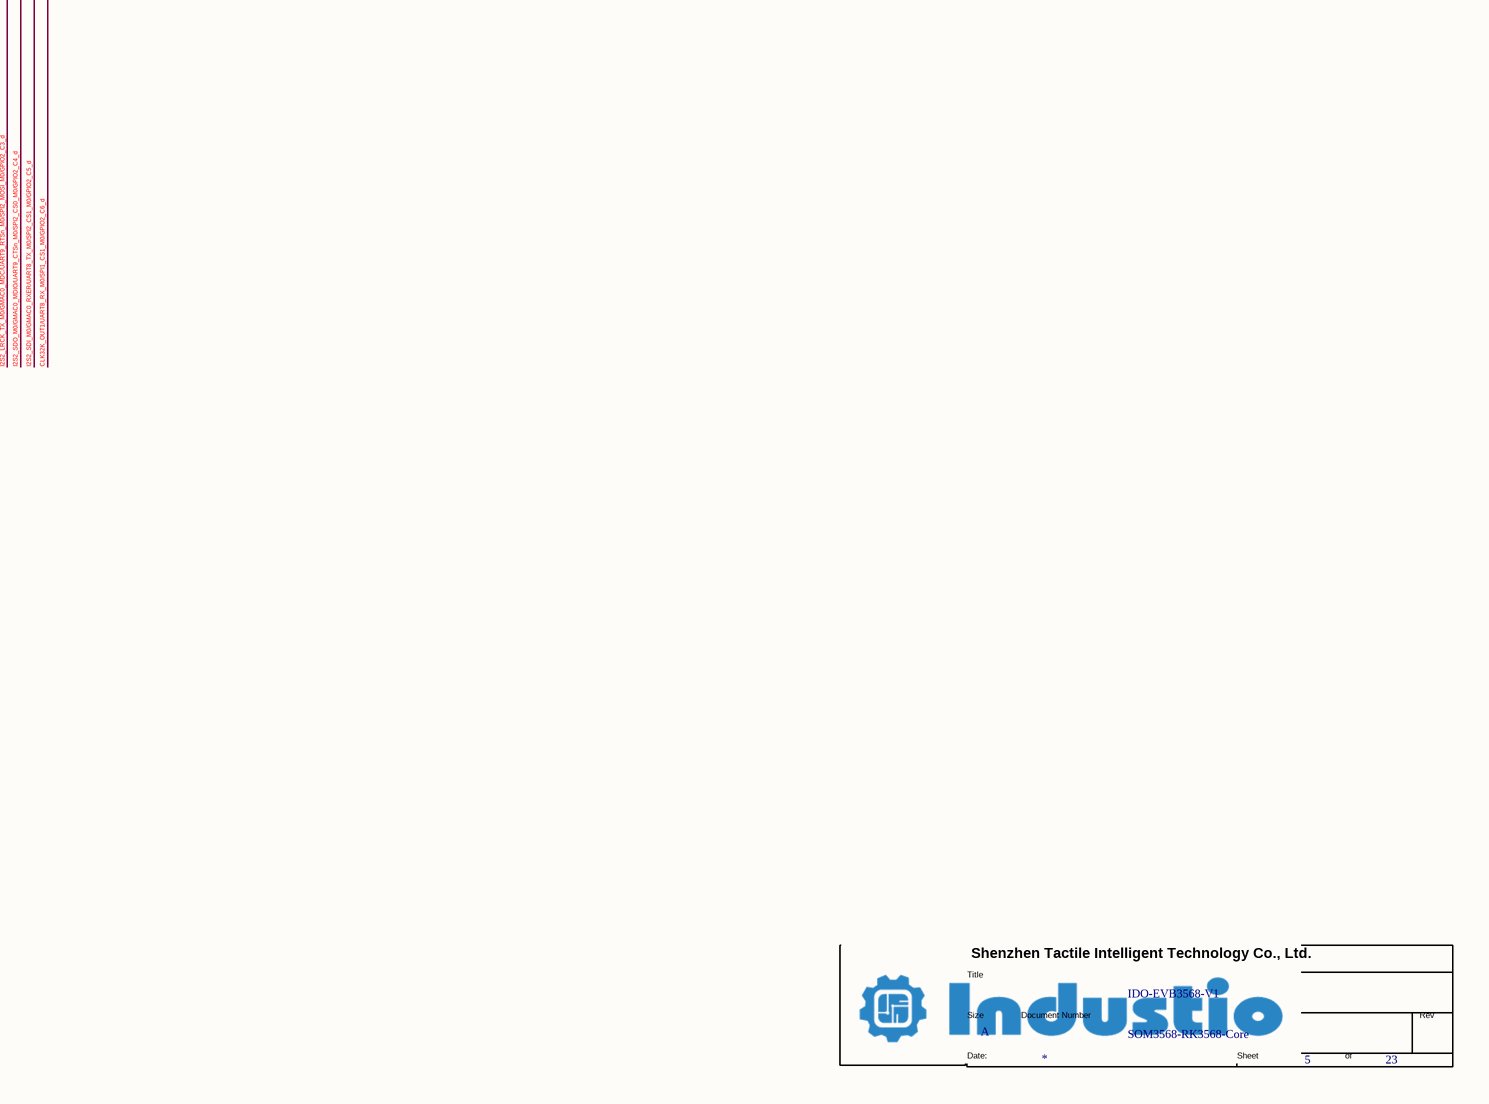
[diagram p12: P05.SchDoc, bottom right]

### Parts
(Parts that share a designator on the sheet are numbered #1, #2 ... from top to bottom, then left to right.)
*#5  Doc: SOM3568-RK3568-Core  Title: IDO-EVB3568-V1  Page Size: A  Page Number: 5  Page Count: 23  (hidden comment: TitleBlock1)  (graphical)
C30  10uF  DSC2: 10V  [1206]
C31  10uF  DSC2: 10V  [1206]
C32  10uF  DSC2: 10V  [1206]
C33  10uF  DSC2: 10V  [1206]
M5  IDO-SOM3568  [SOM3568-204P]

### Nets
GND: C30.1 C31.1 C32.1 C33.1 M5.4(GND1) M5.5(GND2) M5.14(GND3) M5.38(GND4) M5.98(GND5) M5.105(GND6) M5.127(GND7) M5.152(GND8) M5.179(GND9) M5.194(GND10)
VCC3V3_SD: M5.69(VCC3V3_SD)
VCC5V0_SYS: C30.2 C31.2 C32.2 C33.2 M5.1(VCC5V0_RTC) M5.2(VCC5V0_SYS1) M5.3(VCC5V0_SYS2)
VCC_1V8: M5.103(VCC_1V8)
VCC_3V3: M5.104(VCC_3V3)
4G_5G_RESET_GPIO3_A4: M5.123(LCDC_D11/VOP_BT1120_D3/GMAC1_RXD2_M0/I2S3_LRCK_M0/SDMMC2_D3_M1/GPIO3_A4_d) ; off-sheet 4G_5G_RESET_GPIO3_A4  [also labelled LCDC_D11/VOP_BT1120_D3/GMAC1_RXD2_M0/I2S3_LRCK_M0/SDMMC2_D3_M1/GPIO3_A4_d]  [project net 4G_5G_RESET]
BT_REG_ON_H_GPIO3_A7: M5.120(LCDC_D14/VOP_BT1120_D5/GMAC1_RXCLK_M0/SDMMC2_DET_M1/GPIO3_A7_d) ; off-sheet BT_REG_ON_H_GPIO3_A7  [also labelled LCDC_D14/VOP_BT1120_D5/GMAC1_RXCLK_M0/SDMMC2_DET_M1/GPIO3_A7_d]
BT_WAKE_HOST_H_GPIO3_A1: M5.126(LCDC_D8/VOP_BT1120_D0/SPI1_CS0_M1/PCIE30X1_PERSTn_M1/SDMMC2_D0_M1/GPIO3_A1_d) ; off-sheet BT_WAKE_HOST_H_GPIO3_A1  [also labelled LCDC_D8/VOP_BT1120_D0/SPI1_CS0_M1/PCIE30X1_PERSTn_M1/SDMMC2_D0_M1/GPIO3_A1_d]
CAM_CLKOUT0/EBC_SDCE1/GMAC1_RXD0_M1/SPI3_CS1_M0/I2S1_LRCK_RX_M1/GPIO4_A7_d: M5.80(CAM_CLKOUT0/EBC_SDCE1/GMAC1_RXD0_M1/SPI3_CS1_M0/I2S1_LRCK_RX_M1/GPIO4_A7_d) ; off-sheet GMAC1_RXD0_M1  [also labelled GMAC1_RXD0_M1]
CAM_CLKOUT1/EBC_SDCE2/GMAC1_RXD1_M1/SPI3_MISO_M0/I2S1_SDO1_M1/GPIO4_B0_d: M5.79(CAM_CLKOUT1/EBC_SDCE2/GMAC1_RXD1_M1/SPI3_MISO_M0/I2S1_SDO1_M1/GPIO4_B0_d) ; off-sheet GMAC1_RXD1_M1  [also labelled GMAC1_RXD1_M1]
CAN1_RX_M0: M5.36(I2C3_SDA_M0/UART3_RX_M0/CAN1_RX_M0/AUDIOPWM_LOUT_P/ACODEC_ADC_DATA/GPIO1_A0_u) ; off-sheet CAN1_RX_M0  [also labelled I2C3_SDA_M0/UART3_RX_M0/CAN1_RX_M0/AUDIOPWM_LOUT_P/ACODEC_ADC_DATA/GPIO1_A0_u]
CAN1_TX_M0: M5.37(I2C3_SCL_M0/UART3_TX_M0/CAN1_TX_M0/AUDIOPWM_LOUT_N/ACODEC_ADC_CLK/GPIO1_A1_u) ; off-sheet CAN1_TX_M0  [also labelled I2C3_SCL_M0/UART3_TX_M0/CAN1_TX_M0/AUDIOPWM_LOUT_N/ACODEC_ADC_CLK/GPIO1_A1_u]
CAN2_RX_M0: M5.75(I2C2_SDA_M1/EBC_GDSP/CAN2_RX_M0/ISP_FLASH_TRIGIN/VOP_BT656_CLK_M1/GPIO4_B4_d) ; off-sheet CAN2_RX_M0  [also labelled I2C2_SDA_M1/EBC_GDSP/CAN2_RX_M0/ISP_FLASH_TRIGIN/VOP_BT656_CLK_M1/GPIO4_B4_d]
CAN2_TX_M0: M5.74(I2C2_SCL_M1/EBC_SDSHR/CAN2_TX_M0/I2S1_SDO3_M1/GPIO4_B5_d) ; off-sheet CAN2_TX_M0  [also labelled I2C2_SCL_M1/EBC_SDSHR/CAN2_TX_M0/I2S1_SDO3_M1/GPIO4_B5_d]
CIF_CLKIN/EBC_SDCLK/GMAC1_MCLKINOUT_M1/UART1_CTSn_M1/I2S2_SCLK_RX_M1/GPIO4_C1_d: M5.70(CIF_CLKIN/EBC_SDCLK/GMAC1_MCLKINOUT_M1/UART1_CTSn_M1/I2S2_SCLK_RX_M1/GPIO4_C1_d) ; off-sheet GMAC1_MCLKINOUT_M1  [also labelled GMAC1_MCLKINOUT_M1]
CIF_CLKOUT/EBC_GDCLK/PWM11_IR_M1/GPIO4_C0_d: M5.71(CIF_CLKOUT/EBC_GDCLK/PWM11_IR_M1/GPIO4_C0_d) ; off-sheet CIF_CLKOUT_SOC  [also labelled CIF_CLKOUT_SOC]
CIF_D0/EBC_SDDO0/SDMMC2_D0_M0/I2S1_MCLK_M1/VOP_BT656_D0_M1/GPIO3_C6_d: M5.97(CIF_D0/EBC_SDDO0/SDMMC2_D0_M0/I2S1_MCLK_M1/VOP_BT656_D0_M1/GPIO3_C6_d) ; off-sheet SDMMC2_D0_M0  [also labelled SDMMC2_D0_M0]
CIF_D1/EBC_SDDO1/SDMMC2_D1_M0/I2S1_SCLK_TX_M1/VOP_BT656_D1_M1/GPIO3_C7_d: M5.96(CIF_D1/EBC_SDDO1/SDMMC2_D1_M0/I2S1_SCLK_TX_M1/VOP_BT656_D1_M1/GPIO3_C7_d) ; off-sheet SDMMC2_D1_M0  [also labelled SDMMC2_D1_M0]
CIF_D2/EBC_SDDO2/SDMMC2_D2_M0/I2S1_LRCK_TX_M1/VOP_BT656_D2_M1/GPIO3_D0_d: M5.95(CIF_D2/EBC_SDDO2/SDMMC2_D2_M0/I2S1_LRCK_TX_M1/VOP_BT656_D2_M1/GPIO3_D0_d) ; off-sheet SDMMC2_D2_M0  [also labelled SDMMC2_D2_M0]
CIF_D3/EBC_SDDO3/SDMMC2_D3_M0/I2S1_SDO0_M1/VOP_BT656_D3_M1/GPIO3_D1_d: M5.94(CIF_D3/EBC_SDDO3/SDMMC2_D3_M0/I2S1_SDO0_M1/VOP_BT656_D3_M1/GPIO3_D1_d) ; off-sheet SDMMC2_D3_M0  [also labelled SDMMC2_D3_M0]
CIF_D4/EBC_SDDO4/SDMMC2_CMD_M0/I2S1_SDI0_M1/VOP_BT656_D4_M1/GPIO3_D2_d: M5.93(CIF_D4/EBC_SDDO4/SDMMC2_CMD_M0/I2S1_SDI0_M1/VOP_BT656_D4_M1/GPIO3_D2_d) ; off-sheet SDMMC2_CMD_M0  [also labelled SDMMC2_CMD_M0]
CIF_D5/EBC_SDDO5/SDMMC2_CLK_M0/I2S1_SDI1_M1/VOP_BT656_D5_M1/GPIO3_D3_d: M5.92(CIF_D5/EBC_SDDO5/SDMMC2_CLK_M0/I2S1_SDI1_M1/VOP_BT656_D5_M1/GPIO3_D3_d) ; off-sheet SDMMC2_CLK_M0  [also labelled SDMMC2_CLK_M0]
CIF_D6/EBC_SDDO6/SDMMC2_DET_M0/I2S1_SDI2_M1/VOP_BT656_D6_M1/GPIO3_D4_d: M5.91(CIF_D6/EBC_SDDO6/SDMMC2_DET_M0/I2S1_SDI2_M1/VOP_BT656_D6_M1/GPIO3_D4_d) ; off-sheet WIFI_REG_ON_H_GPIO3_D4  [also labelled WIFI_REG_ON_H_GPIO3_D4]
CIF_D7/EBC_SDDO7/SDMMC2_PWREN_M0/I2S1_SDI3_M1/VOP_BT656_D7_M1/GPIO3_D5_d: M5.90(CIF_D7/EBC_SDDO7/SDMMC2_PWREN_M0/I2S1_SDI3_M1/VOP_BT656_D7_M1/GPIO3_D5_d) ; off-sheet WIFI_WAKE_HOST_H_GPIO3_D5  [also labelled WIFI_WAKE_HOST_H_GPIO3_D5]
CIF_D8/EBC_SDDO8/GMAC1_TXD2_M1/UART1_TX_M1/PDM_CLK0_M1/GPIO3_D6_d: M5.89(CIF_D8/EBC_SDDO8/GMAC1_TXD2_M1/UART1_TX_M1/PDM_CLK0_M1/GPIO3_D6_d) ; off-sheet GMAC1_TXD2_M1  [also labelled GMAC1_TXD2_M1]
CIF_D9/EBC_SDDO9/GMAC1_TXD3_M1/UART1_RX_M1/PDM_SDI0_M1/GPIO3_D7_d: M5.88(CIF_D9/EBC_SDDO9/GMAC1_TXD3_M1/UART1_RX_M1/PDM_SDI0_M1/GPIO3_D7_d) ; off-sheet GMAC1_TXD3_M1  [also labelled GMAC1_TXD3_M1]
CIF_D10/EBC_SDDO10/GMAC1_TXCLK_M1/PDM_CLK1_M1/GPIO4_A0_d: M5.87(CIF_D10/EBC_SDDO10/GMAC1_TXCLK_M1/PDM_CLK1_M1/GPIO4_A0_d) ; off-sheet GMAC1_TXCLK_M1  [also labelled GMAC1_TXCLK_M1]
CIF_D11/EBC_SDDO11/GMAC1_RXD2_M1/PDM_SDI1_M1/GPIO4_A1_d: M5.86(CIF_D11/EBC_SDDO11/GMAC1_RXD2_M1/PDM_SDI1_M1/GPIO4_A1_d) ; off-sheet GMAC1_RXD2_M1  [also labelled GMAC1_RXD2_M1]
CIF_D12/EBC_SDDO12/GMAC1_RXD3_M1/UART7_TX_M2/PDM_SDI2_M1/GPIO4_A2_d: M5.85(CIF_D12/EBC_SDDO12/GMAC1_RXD3_M1/UART7_TX_M2/PDM_SDI2_M1/GPIO4_A2_d) ; off-sheet GMAC1_RXD3_M1  [also labelled GMAC1_RXD3_M1]
CIF_D13/EBC_SDDO13/GMAC1_RXCLK_M1/UART7_RX_M2/PDM_SDI3_M1/GPIO4_A3_d: M5.84(CIF_D13/EBC_SDDO13/GMAC1_RXCLK_M1/UART7_RX_M2/PDM_SDI3_M1/GPIO4_A3_d) ; off-sheet GMAC1_RXCLK_M1  [also labelled GMAC1_RXCLK_M1]
CIF_D14/EBC_SDDO14/GMAC1_TXD0_M1/UART9_TX_M2/I2S2_LRCK_TX_M1/GPIO4_A4_d: M5.83(CIF_D14/EBC_SDDO14/GMAC1_TXD0_M1/UART9_TX_M2/I2S2_LRCK_TX_M1/GPIO4_A4_d) ; off-sheet GMAC1_TXD0_M1  [also labelled GMAC1_TXD0_M1]
CIF_D15/EBC_SDDO15/GMAC1_TXD1_M1/UART9_RX_M2/I2S2_LRCK_RX_M1/GPIO4_A5_d: M5.82(CIF_D15/EBC_SDDO15/GMAC1_TXD1_M1/UART9_RX_M2/I2S2_LRCK_RX_M1/GPIO4_A5_d) ; off-sheet GMAC1_TXD1_M1  [also labelled GMAC1_TXD1_M1]
CIF_HREF/EBC_SDLE/GMAC1_MDC_M1/UART1_RTSn_M1/I2S2_MCLK_M1/GPIO4_B6_d: M5.73(CIF_HREF/EBC_SDLE/GMAC1_MDC_M1/UART1_RTSn_M1/I2S2_MCLK_M1/GPIO4_B6_d) ; off-sheet GMAC1_MDC_M1  [also labelled GMAC1_MDC_M1]
CIF_VSYNC/EBC_SDOE/GMAC1_MDIO_M1/I2S2_SCLK_TX_M1/GPIO4_B7_d: M5.72(CIF_VSYNC/EBC_SDOE/GMAC1_MDIO_M1/I2S2_SCLK_TX_M1/GPIO4_B7_d) ; off-sheet GMAC1_MDIO_M1  [also labelled GMAC1_MDIO_M1]
CLK32K_OUT1/UART8_RX_M0/SPI1_CS1_M0/GPIO2_C6_d: M5.58(CLK32K_OUT1/UART8_RX_M0/SPI1_CS1_M0/GPIO2_C6_d) ; off-sheet UART8_RX_M0  [also labelled UART8_RX_M0]
EDP_HPDIN_M0/SPDIF_TX_M2/SATA2_ACT_LED/PCIE30X2_PERSTn_M2/I2S3_LRCK_M1/GPIO4_C4_d: M5.29(EDP_HPDIN_M0/SPDIF_TX_M2/SATA2_ACT_LED/PCIE30X2_PERSTn_M2/I2S3_LRCK_M1/GPIO4_C4_d) ; off-sheet PCA9539_INT_GPIO4_C4  [also labelled PCA9539_INT_GPIO4_C4]
EDP_PWM4: M5.22(PWM4/VOP_PWM_M0/PCIE30X1_PERSTn_M0/MCU_JTAG_TRSTn/GPIO0_C3_d) ; off-sheet EDP_PWM4  [also labelled PWM4/VOP_PWM_M0/PCIE30X1_PERSTn_M0/MCU_JTAG_TRSTn/GPIO0_C3_d]
EDP_TX_AUXN: M5.197(EDP_TX_AUXN) ; off-sheet EDP_TX_AUXN
EDP_TX_AUXP: M5.198(EDP_TX_AUXP) ; off-sheet EDP_TX_AUXP
EDP_TX_D0N: M5.203(EDP_TX_D0N) ; off-sheet EDP_TX_D0N
EDP_TX_D0P: M5.204(EDP_TX_D0P) ; off-sheet EDP_TX_D0P
EDP_TX_D1N: M5.201(EDP_TX_D1N) ; off-sheet EDP_TX_D1N
EDP_TX_D1P: M5.202(EDP_TX_D1P) ; off-sheet EDP_TX_D1P
EDP_TX_D2N: M5.199(EDP_TX_D2N) ; off-sheet EDP_TX_D2N
EDP_TX_D2P: M5.200(EDP_TX_D2P) ; off-sheet EDP_TX_D2P
EDP_TX_D3N: M5.195(EDP_TX_D3N) ; off-sheet EDP_TX_D3N
EDP_TX_D3P: M5.196(EDP_TX_D3P) ; off-sheet EDP_TX_D3P
EXT_EN: M5.7(EXT_EN) ; off-sheet EXT_EN
GMAC0_INT/PMEB_GPIO3_B0: M5.119(LCDC_D15/VOP_BT1120_D6/ETH1_REFCLKO_25M_M0/SDMMC2_PWREN_M1/GPIO3_B0_d) ; off-sheet GMAC0_INT/PMEB_GPIO3_B0  [also labelled LCDC_D15/VOP_BT1120_D6/ETH1_REFCLKO_25M_M0/SDMMC2_PWREN_M1/GPIO3_B0_d]
GMAC0_MCLKINOUT: M5.54(I2S2_SCLK_TX_M0/GMAC0_MCLKINOUT/UART7_CTSn_M0/SPI2_MISO_M0/GPIO2_C2_d) ; off-sheet GMAC0_MCLKINOUT  [also labelled I2S2_SCLK_TX_M0/GMAC0_MCLKINOUT/UART7_CTSn_M0/SPI2_MISO_M0/GPIO2_C2_d]
GMAC0_MDC: M5.55(I2S2_LRCK_TX_M0/GMAC0_MDC/UART9_RTSn_M0/SPI2_MOSI_M0/GPIO2_C3_d) ; off-sheet GMAC0_MDC  [also labelled I2S2_LRCK_TX_M0/GMAC0_MDC/UART9_RTSn_M0/SPI2_MOSI_M0/GPIO2_C3_d]
GMAC0_MDIO: M5.56(I2S2_SDO_M0/GMAC0_MDIO/UART9_CTSn_M0/SPI2_CS0_M0/GPIO2_C4_d) ; off-sheet GMAC0_MDIO  [also labelled I2S2_SDO_M0/GMAC0_MDIO/UART9_CTSn_M0/SPI2_CS0_M0/GPIO2_C4_d]
GMAC0_RSTn_GPIO3_A5: M5.122(LCDC_D12/VOP_BT1120_D4/GMAC1_RXD3_M0/I2S3_SDO_M0/SDMMC2_CMD_M1/GPIO3_A5_d) ; off-sheet GMAC0_RSTn_GPIO3_A5  [also labelled LCDC_D12/VOP_BT1120_D4/GMAC1_RXD3_M0/I2S3_SDO_M0/SDMMC2_CMD_M1/GPIO3_A5_d]
GMAC0_RXCLK: M5.41(SDMMC1_D2/GMAC0_RXCLK/UART7_RX_M0/GPIO2_A5_u) ; off-sheet GMAC0_RXCLK  [also labelled SDMMC1_D2/GMAC0_RXCLK/UART7_RX_M0/GPIO2_A5_u]
GMAC0_RXD0: M5.50(GMAC0_RXD0/UART1_CTSn_M0/SPI1_MISO_M0/GPIO2_B6_u) ; off-sheet GMAC0_RXD0  [also labelled GMAC0_RXD0/UART1_CTSn_M0/SPI1_MISO_M0/GPIO2_B6_u]
GMAC0_RXD1: M5.51(I2S2_SCLK_RX_M0/GMAC0_RXD1/UART6_RTSn_M0/SPI1_MOSI_M0/GPIO2_B7_d) ; off-sheet GMAC0_RXD1  [also labelled I2S2_SCLK_RX_M0/GMAC0_RXD1/UART6_RTSn_M0/SPI1_MOSI_M0/GPIO2_B7_d]
GMAC0_RXD2: M5.39(SDMMC1_D0/GMAC0_RXD2/UART6_RX_M0/GPIO2_A3_u) ; off-sheet GMAC0_RXD2  [also labelled SDMMC1_D0/GMAC0_RXD2/UART6_RX_M0/GPIO2_A3_u]
GMAC0_RXD3: M5.40(SDMMC1_D1/GMAC0_RXD3/UART6_TX_M0/GPIO2_A4_u) ; off-sheet GMAC0_RXD3  [also labelled SDMMC1_D1/GMAC0_RXD3/UART6_TX_M0/GPIO2_A4_u]
GMAC0_RXDV_CRS: M5.52(I2S2_LRCK_RX_M0/GMAC0_RXDV_CRS/UART6_CTSn_M0/SPI1_CS0_M0/GPIO2_C0_d) ; off-sheet GMAC0_RXDV_CRS  [also labelled I2S2_LRCK_RX_M0/GMAC0_RXDV_CRS/UART6_CTSn_M0/SPI1_CS0_M0/GPIO2_C0_d]
GMAC0_TXCLK: M5.44(SDMMC1_CLK/GMAC0_TXCLK/UART9_TX_M0/GPIO2_B0_d) ; off-sheet GMAC0_TXCLK  [also labelled SDMMC1_CLK/GMAC0_TXCLK/UART9_TX_M0/GPIO2_B0_d]
GMAC0_TXD0: M5.47(GMAC0_TXD0/UART1_RX_M0/GPIO2_B3_u) ; off-sheet GMAC0_TXD0  [also labelled GMAC0_TXD0/UART1_RX_M0/GPIO2_B3_u]
GMAC0_TXD1: M5.48(GMAC0_TXD1/UART1_TX_M0/GPIO2_B4_u) ; off-sheet GMAC0_TXD1  [also labelled GMAC0_TXD1/UART1_TX_M0/GPIO2_B4_u]
GMAC0_TXD2: M5.42(SDMMC1_D3/GMAC0_TXD2/UART7_TX_M0/GPIO2_A6_u) ; off-sheet GMAC0_TXD2  [also labelled SDMMC1_D3/GMAC0_TXD2/UART7_TX_M0/GPIO2_A6_u]
GMAC0_TXD3: M5.43(SDMMC1_CMD/GMAC0_TXD3/UART9_RX_M0/GPIO2_A7_u) ; off-sheet GMAC0_TXD3  [also labelled SDMMC1_CMD/GMAC0_TXD3/UART9_RX_M0/GPIO2_A7_u]
GMAC0_TXEN: M5.49(GMAC0_TXEN/UART1_RTSn_M0/SPI1_CLK_M0/GPIO2_B5_u) ; off-sheet GMAC0_TXEN  [also labelled GMAC0_TXEN/UART1_RTSn_M0/SPI1_CLK_M0/GPIO2_B5_u]
GMAC1_INT/PMEB_GPIO3_C1: M5.110(LCDC_HSYNC/VOP_BT1120_D13/SPI1_MOSI_M1/PCIE20_PERSTn_M1/I2S1_SDO2_M2/GPIO3_C1_d) ; off-sheet GMAC1_INT/PMEB_GPIO3_C1  [also labelled LCDC_HSYNC/VOP_BT1120_D13/SPI1_MOSI_M1/PCIE20_PERSTn_M1/I2S1_SDO2_M2/GPIO3_C1_d]
GMAC1_RSTn_GPIO3_A6: M5.121(LCDC_D13/VOP_BT1120_CLK/GMAC1_TXCLK_M0/I2S3_SDI_M0/SDMMC2_CLK_M1/GPIO3_A6_d) ; off-sheet GMAC1_RSTn_GPIO3_A6  [also labelled LCDC_D13/VOP_BT1120_CLK/GMAC1_TXCLK_M0/I2S3_SDI_M0/SDMMC2_CLK_M1/GPIO3_A6_d]
GMAC1_RXDV_CRS_M1: M5.78(ISP_PRELIGHT_TRIG/EBC_SDCE3/GMAC1_RXDV_CRS_M1/I2S1_SDO2_M1/GPIO4_B1_d) ; off-sheet GMAC1_RXDV_CRS_M1  [also labelled ISP_PRELIGHT_TRIG/EBC_SDCE3/GMAC1_RXDV_CRS_M1/I2S1_SDO2_M1/GPIO4_B1_d]
GMAC1_TXEN_M1: M5.81(ISP_FLASHTRIGOUT/EBC_SDCE0/GMAC1_TXEN_M1/SPI3_CS0_M0/I2S1_SCLK_RX_M1/GPIO4_A6_d) ; off-sheet GMAC1_TXEN_M1  [also labelled ISP_FLASHTRIGOUT/EBC_SDCE0/GMAC1_TXEN_M1/SPI3_CS0_M0/I2S1_SCLK_RX_M1/GPIO4_A6_d]
HDMI_TX_CLKN: M5.153(HDMI_TX_CLKN) ; off-sheet HDMI_TX_CLKN
HDMI_TX_CLKP: M5.154(HDMI_TX_CLKP) ; off-sheet HDMI_TX_CLKP
HDMI_TX_D0N: M5.155(HDMI_TX_D0N) ; off-sheet HDMI_TX_D0N
HDMI_TX_D0P: M5.156(HDMI_TX_D0P) ; off-sheet HDMI_TX_D0P
HDMI_TX_D1N: M5.157(HDMI_TX_D1N) ; off-sheet HDMI_TX_D1N
HDMI_TX_D1P: M5.158(HDMI_TX_D1P) ; off-sheet HDMI_TX_D1P
HDMI_TX_D2N: M5.159(HDMI_TX_D2N) ; off-sheet HDMI_TX_D2N
HDMI_TX_D2P: M5.160(HDMI_TX_D2P) ; off-sheet HDMI_TX_D2P
HDMI_TX_HPDIN: M5.148(HDMI_TX_HPDIN) ; off-sheet HDMI_TX_HPDIN
HDMITX_CEC_M0: M5.151(HDMITX_CEC_M0/SPI3_CS1_M1/GPIO4_D1_u) ; off-sheet HDMITX_CEC_M0  [also labelled HDMITX_CEC_M0/SPI3_CS1_M1/GPIO4_D1_u]
HDMITX_CEC_M1/PWM0_M1/UART0_CTSn/GPIO0_C7_d: M5.26(HDMITX_CEC_M1/PWM0_M1/UART0_CTSn/GPIO0_C7_d) ; off-sheet SYS_LED_GPIO0_C7  [also labelled SYS_LED_GPIO0_C7]
HDMITX_SCL/I2C5_SCL_M1/GPIO4_C7_u: M5.150(HDMITX_SCL/I2C5_SCL_M1/GPIO4_C7_u) ; off-sheet I2C5_SCL-HDMI  [also labelled I2C5_SCL-HDMI]
HDMITX_SDA/I2C5_SDA_M1/GPIO4_D0_u: M5.149(HDMITX_SDA/I2C5_SDA_M1/GPIO4_D0_u) ; off-sheet I2C5_SDA-HDMI  [also labelled I2C5_SDA-HDMI]
HOST_WAKE_BT_H_GPIO3_A2: M5.125(LCDC_D9/VOP_BT1120_D1/GMAC1_TXD2_M0/I2S3_MCLK_M0/SDMMC2_D1_M1/GPIO3_A2_d) ; off-sheet HOST_WAKE_BT_H_GPIO3_A2  [also labelled LCDC_D9/VOP_BT1120_D1/GMAC1_TXD2_M0/I2S3_MCLK_M0/SDMMC2_D1_M1/GPIO3_A2_d]
HP_DET_H_GPIO0_C5: M5.24(PWM6/SPI0_MISO_M0/PCIE30X2_WAKEn_M0/GPIO0_C5_d) ; off-sheet HP_DET_H_GPIO0_C5  [also labelled PWM6/SPI0_MISO_M0/PCIE30X2_WAKEn_M0/GPIO0_C5_d]
HP_SNS: M5.10(HP_SNS) ; off-sheet HP_SNS
HPL_OUT: M5.9(HPL_OUT) ; off-sheet HPL_OUT
HPR_OUT: M5.11(HPR_OUT) ; off-sheet HPR_OUT
I2C1_SCL: M5.32(I2C1_SCL/CAN0_TX_M0/PCIE30X1_BUTTONRSTn/MCU_JTAG_TDO/GPIO0_B3_u) ; off-sheet I2C1_SCL  [also labelled I2C1_SCL/CAN0_TX_M0/PCIE30X1_BUTTONRSTn/MCU_JTAG_TDO/GPIO0_B3_u]
I2C1_SDA: M5.33(I2C1_SDA/CAN0_RX_M0/PCIE20_BUTTONRSTn/MCU_JTAG_TCK/GPIO0_B4_u) ; off-sheet I2C1_SDA  [also labelled I2C1_SDA/CAN0_RX_M0/PCIE20_BUTTONRSTn/MCU_JTAG_TCK/GPIO0_B4_u]
I2C2_SCL_M0: M5.34(I2C2_SCL_M0/SPI0_CLK_M0/PCIE20_WAKEn_M0/PWM1_M1/GPIO0_B5_u) ; off-sheet I2C2_SCL_M0  [also labelled I2C2_SCL_M0/SPI0_CLK_M0/PCIE20_WAKEn_M0/PWM1_M1/GPIO0_B5_u]
I2C2_SDA_M0: M5.35(I2C2_SDA_M0/SPI0_MOSI_M0/PCIE20_PERSTn_M0/PWM2_M1/GPIO0_B6_u) ; off-sheet I2C2_SDA_M0  [also labelled I2C2_SDA_M0/SPI0_MOSI_M0/PCIE20_PERSTn_M0/PWM2_M1/GPIO0_B6_u]
I2C3_SCL_M1: M5.114(LCDC_D20/VOP_BT1120_D11/GMAC1_TXD0_M0/I2C3_SCL_M1/PWM10_M0/GPIO3_B5_d) ; off-sheet I2C3_SCL_M1  [also labelled LCDC_D20/VOP_BT1120_D11/GMAC1_TXD0_M0/I2C3_SCL_M1/PWM10_M0/GPIO3_B5_d]
I2C3_SDA_M1: M5.113(LCDC_D21/VOP_BT1120_D12/GMAC1_TXD1_M0/I2C3_SDA_M1/PWM11_IR_M0/GPIO3_B6_d) ; off-sheet I2C3_SDA_M1  [also labelled LCDC_D21/VOP_BT1120_D12/GMAC1_TXD1_M0/I2C3_SDA_M1/PWM11_IR_M0/GPIO3_B6_d]
I2C4_SCL_M0/EBC_GDOE/ETH1_REFCLKO_25M_M1/SPI3_CLK_M0/I2S2_SDO_M1/GPIO4_B3_d: M5.76(I2C4_SCL_M0/EBC_GDOE/ETH1_REFCLKO_25M_M1/SPI3_CLK_M0/I2S2_SDO_M1/GPIO4_B3_d) ; off-sheet I2C4_SCL_M0  [also labelled I2C4_SCL_M0]
I2C4_SDA_M0/EBC_VCOM/GMAC1_RXER_M1/SPI3_MOSI_M0/I2S2_SDI_M1/GPIO4_B2_d: M5.77(I2C4_SDA_M0/EBC_VCOM/GMAC1_RXER_M1/SPI3_MOSI_M0/I2S2_SDI_M1/GPIO4_B2_d) ; off-sheet I2C4_SDA_M0  [also labelled I2C4_SDA_M0]
I2S2_MCLK_M0/ETH0_REFCLKO_25M/UART7_RTSn_M0/SPI2_CLK_M0/GPIO2_C1_d: M5.53(I2S2_MCLK_M0/ETH0_REFCLKO_25M/UART7_RTSn_M0/SPI2_CLK_M0/GPIO2_C1_d) ; off-sheet MIPI_CAM0_PDN_L_GPIO2_C1  [also labelled MIPI_CAM0_PDN_L_GPIO2_C1]
I2S2_SDI_M0/GMAC0_RXER/UART8_TX_M0/SPI2_CS1_M0/GPIO2_C5_d: M5.57(I2S2_SDI_M0/GMAC0_RXER/UART8_TX_M0/SPI2_CS1_M0/GPIO2_C5_d) ; off-sheet UART8_TX_M0  [also labelled UART8_TX_M0]
LCDC_D10/VOP_BT1120_D2/GMAC1_TXD3_M0/I2S3_SCLK_M0/SDMMC2_D2_M1/GPIO3_A3_d: M5.124(LCDC_D10/VOP_BT1120_D2/GMAC1_TXD3_M0/I2S3_SCLK_M0/SDMMC2_D2_M1/GPIO3_A3_d) ; off-sheet CIF_RST_GPIO3_A3  [also labelled CIF_RST_GPIO3_A3]
LCDC_D16/VOP_BT1120_D7/GMAC1_RXD0_M0/UART4_RX_M1/PWM8_M0/GPIO3_B1_d: M5.118(LCDC_D16/VOP_BT1120_D7/GMAC1_RXD0_M0/UART4_RX_M1/PWM8_M0/GPIO3_B1_d) ; off-sheet UART4_RX_M1  [also labelled UART4_RX_M1]
LCDC_D17/VOP_BT1120_D8/GMAC1_RXD1_M0/UART4_TX_M1/PWM9_M0/GPIO3_B2_d: M5.117(LCDC_D17/VOP_BT1120_D8/GMAC1_RXD1_M0/UART4_TX_M1/PWM9_M0/GPIO3_B2_d) ; off-sheet UART4_TX_M1  [also labelled UART4_TX_M1]
LCDC_D18/VOP_BT1120_D9/GMAC1_RXDV_CRS_M0/I2C5_SCL_M0/PDM_SDI0_M2/GPIO3_B3_d: M5.116(LCDC_D18/VOP_BT1120_D9/GMAC1_RXDV_CRS_M0/I2C5_SCL_M0/PDM_SDI0_M2/GPIO3_B3_d) ; off-sheet TP_RST_L_GPIO3_B3  [also labelled TP_RST_L_GPIO3_B3]
LCDC_D19/VOP_BT1120_D10/GMAC1_RXER_M0/I2C5_SDA_M0/PDM_SDI1_M2/GPIO3_B4_d: M5.115(LCDC_D19/VOP_BT1120_D10/GMAC1_RXER_M0/I2C5_SDA_M0/PDM_SDI1_M2/GPIO3_B4_d) ; off-sheet TP_INT_L_GPIO3_B4  [also labelled TP_INT_L_GPIO3_B4]
LCDC_D22/PWM12_M0/GMAC1_TXEN_M0/UART3_TX_M1/PDM_SDI2_M2/GPIO3_B7_d: M5.112(LCDC_D22/PWM12_M0/GMAC1_TXEN_M0/UART3_TX_M1/PDM_SDI2_M2/GPIO3_B7_d) ; off-sheet UART3_TX_M1  [also labelled UART3_TX_M1]
LCDC_D23/PWM13_M0/GMAC1_MCLKINOUT_M0/UART3_RX_M1/PDM_SDI3_M2/GPIO3_C0_d: M5.111(LCDC_D23/PWM13_M0/GMAC1_MCLKINOUT_M0/UART3_RX_M1/PDM_SDI3_M2/GPIO3_C0_d) ; off-sheet UART3_RX_M1  [also labelled UART3_RX_M1]
LCDC_DEN/VOP_BT1120_D15/SPI1_CLK_M1/UART5_RX_M1/I2S1_SCLK_RX_M2/GPIO3_C3_d: M5.108(LCDC_DEN/VOP_BT1120_D15/SPI1_CLK_M1/UART5_RX_M1/I2S1_SCLK_RX_M2/GPIO3_C3_d) ; off-sheet UART5_RX_M1  [also labelled UART5_RX_M1]
LCDC_VSYNC/VOP_BT1120_D14/SPI1_MISO_M1/UART5_TX_M1/I2S1_SDO3_M2/GPIO3_C2_d: M5.109(LCDC_VSYNC/VOP_BT1120_D14/SPI1_MISO_M1/UART5_TX_M1/I2S1_SDO3_M2/GPIO3_C2_d) ; off-sheet UART5_TX_M1  [also labelled UART5_TX_M1]
LVDS_PWM5: M5.23(PWM5/SPI0_CS1_M0/UART0_RTSn/GPIO0_C4_d) ; off-sheet LVDS_PWM5  [also labelled PWM5/SPI0_CS1_M0/UART0_RTSn/GPIO0_C4_d]
MIC1_INN: M5.13(MIC1_INN) ; off-sheet MIC1_INN
MIC1_INP: M5.12(MIC1_INP) ; off-sheet MIC1_INP
MIPI_CSI_RX_CLK0N/PCIE30_REFCLKN_IN: M5.170(MIPI_CSI_RX_CLK0N/PCIE30_REFCLKN_IN) ; off-sheet MIPI_CSI_RX_CLK0N  [also labelled MIPI_CSI_RX_CLK0N]
MIPI_CSI_RX_CLK0P/PCIE30_REFCLKP_IN: M5.169(MIPI_CSI_RX_CLK0P/PCIE30_REFCLKP_IN) ; off-sheet MIPI_CSI_RX_CLK0P  [also labelled MIPI_CSI_RX_CLK0P]
MIPI_CSI_RX_CLK1N: M5.172(MIPI_CSI_RX_CLK1N) ; off-sheet MIPI_CSI_RX_CLK1N
MIPI_CSI_RX_CLK1P: M5.171(MIPI_CSI_RX_CLK1P) ; off-sheet MIPI_CSI_RX_CLK1P
MIPI_CSI_RX_D0N/PCIE30_TX0N: M5.162(MIPI_CSI_RX_D0N/PCIE30_TX0N) ; off-sheet MIPI_CSI_RX_D0N  [also labelled MIPI_CSI_RX_D0N]
MIPI_CSI_RX_D0P/PCIE30_TX0P: M5.161(MIPI_CSI_RX_D0P/PCIE30_TX0P) ; off-sheet MIPI_CSI_RX_D0P  [also labelled MIPI_CSI_RX_D0P]
MIPI_CSI_RX_D1N/PCIE30_TX1N: M5.164(MIPI_CSI_RX_D1N/PCIE30_TX1N) ; off-sheet MIPI_CSI_RX_D1N  [also labelled MIPI_CSI_RX_D1N]
MIPI_CSI_RX_D1P/PCIE30_TX1P: M5.163(MIPI_CSI_RX_D1P/PCIE30_TX1P) ; off-sheet MIPI_CSI_RX_D1P  [also labelled MIPI_CSI_RX_D1P]
MIPI_CSI_RX_D2N/PCIE30_RX0N: M5.166(MIPI_CSI_RX_D2N/PCIE30_RX0N) ; off-sheet MIPI_CSI_RX_D2N  [also labelled MIPI_CSI_RX_D2N]
MIPI_CSI_RX_D2P/PCIE30_RX0P: M5.165(MIPI_CSI_RX_D2P/PCIE30_RX0P) ; off-sheet MIPI_CSI_RX_D2P  [also labelled MIPI_CSI_RX_D2P]
MIPI_CSI_RX_D3N/PCIE30_RX1N: M5.168(MIPI_CSI_RX_D3N/PCIE30_RX1N) ; off-sheet MIPI_CSI_RX_D3N  [also labelled MIPI_CSI_RX_D3N]
MIPI_CSI_RX_D3P/PCIE30_RX1P: M5.167(MIPI_CSI_RX_D3P/PCIE30_RX1P) ; off-sheet MIPI_CSI_RX_D3P  [also labelled MIPI_CSI_RX_D3P]
MIPI_DSI_TX0_CLKN: M5.142(MIPI_DSI_TX0_CLKN/LVDS_TX0_CLKN) ; off-sheet MIPI_DSI_TX0_CLKN  [also labelled MIPI_DSI_TX0_CLKN/LVDS_TX0_CLKN]
MIPI_DSI_TX0_CLKP: M5.143(MIPI_DSI_TX0_CLKP/LVDS_TX0_CLKP) ; off-sheet MIPI_DSI_TX0_CLKP  [also labelled MIPI_DSI_TX0_CLKP/LVDS_TX0_CLKP]
MIPI_DSI_TX0_D0N: M5.146(MIPI_DSI_TX0_D0N/LVDS_TX0_D0N) ; off-sheet MIPI_DSI_TX0_D0N  [also labelled MIPI_DSI_TX0_D0N/LVDS_TX0_D0N]
MIPI_DSI_TX0_D0P: M5.147(MIPI_DSI_TX0_D0P/LVDS_TX0_D0P) ; off-sheet MIPI_DSI_TX0_D0P  [also labelled MIPI_DSI_TX0_D0P/LVDS_TX0_D0P]
MIPI_DSI_TX0_D1N: M5.144(MIPI_DSI_TX0_D1N/LVDS_TX0_D1N) ; off-sheet MIPI_DSI_TX0_D1N  [also labelled MIPI_DSI_TX0_D1N/LVDS_TX0_D1N]
MIPI_DSI_TX0_D1P: M5.145(MIPI_DSI_TX0_D1P/LVDS_TX0_D1P) ; off-sheet MIPI_DSI_TX0_D1P  [also labelled MIPI_DSI_TX0_D1P/LVDS_TX0_D1P]
MIPI_DSI_TX0_D2N: M5.140(MIPI_DSI_TX0_D2N/LVDS_TX0_D2N) ; off-sheet MIPI_DSI_TX0_D2N  [also labelled MIPI_DSI_TX0_D2N/LVDS_TX0_D2N]
MIPI_DSI_TX0_D2P: M5.141(MIPI_DSI_TX0_D2P/LVDS_TX0_D2P) ; off-sheet MIPI_DSI_TX0_D2P  [also labelled MIPI_DSI_TX0_D2P/LVDS_TX0_D2P]
MIPI_DSI_TX0_D3N: M5.138(MIPI_DSI_TX0_D3N/LVDS_TX0_D3N) ; off-sheet MIPI_DSI_TX0_D3N  [also labelled MIPI_DSI_TX0_D3N/LVDS_TX0_D3N]
MIPI_DSI_TX0_D3P: M5.139(MIPI_DSI_TX0_D3P/LVDS_TX0_D3P) ; off-sheet MIPI_DSI_TX0_D3P  [also labelled MIPI_DSI_TX0_D3P/LVDS_TX0_D3P]
MIPI_DSI_TX1_CLKN: M5.132(MIPI_DSI_TX1_CLKN) ; off-sheet MIPI_DSI_TX1_CLKN
MIPI_DSI_TX1_CLKP: M5.133(MIPI_DSI_TX1_CLKP) ; off-sheet MIPI_DSI_TX1_CLKP
MIPI_DSI_TX1_D0N: M5.136(MIPI_DSI_TX1_D0N) ; off-sheet MIPI_DSI_TX1_D0N
MIPI_DSI_TX1_D0P: M5.137(MIPI_DSI_TX1_D0P) ; off-sheet MIPI_DSI_TX1_D0P
MIPI_DSI_TX1_D1N: M5.134(MIPI_DSI_TX1_D1N) ; off-sheet MIPI_DSI_TX1_D1N
MIPI_DSI_TX1_D1P: M5.135(MIPI_DSI_TX1_D1P) ; off-sheet MIPI_DSI_TX1_D1P
MIPI_DSI_TX1_D2N: M5.130(MIPI_DSI_TX1_D2N) ; off-sheet MIPI_DSI_TX1_D2N
MIPI_DSI_TX1_D2P: M5.131(MIPI_DSI_TX1_D2P) ; off-sheet MIPI_DSI_TX1_D2P
MIPI_DSI_TX1_D3N: M5.128(MIPI_DSI_TX1_D3N) ; off-sheet MIPI_DSI_TX1_D3N
MIPI_DSI_TX1_D3P: M5.129(MIPI_DSI_TX1_D3P) ; off-sheet MIPI_DSI_TX1_D3P
PCIE20_REFCLKN: M5.178(PCIE20_REFCLKN) ; off-sheet PCIE20_REFCLKN
PCIE20_REFCLKP: M5.177(PCIE20_REFCLKP) ; off-sheet PCIE20_REFCLKP
PCIE20_RXN: M5.176(PCIE20_RXN/SATA2_RXN/QSGMII_RXN_M1) ; off-sheet PCIE20_RXN  [also labelled PCIE20_RXN/SATA2_RXN/QSGMII_RXN_M1]
PCIE20_RXP: M5.175(PCIE20_RXP/SATA2_RXP/QSGMII_RXP_M1) ; off-sheet PCIE20_RXP  [also labelled PCIE20_RXP/SATA2_RXP/QSGMII_RXP_M1]
PCIE20_TXN: M5.174(PCIE20_TXN/SATA2_TXN/QSGMII_TXN_M1) ; off-sheet PCIE20_TXN  [also labelled PCIE20_TXN/SATA2_TXN/QSGMII_TXN_M1]
PCIE20_TXP: M5.173(PCIE20_TXP/SATA2_TXP/QSGMII_TXP_M1) ; off-sheet PCIE20_TXP  [also labelled PCIE20_TXP/SATA2_TXP/QSGMII_TXP_M1]
PWM1_M0/GPUAVS/UART0_RX/GPIO0_C0_d: M5.19(PWM1_M0/GPUAVS/UART0_RX/GPIO0_C0_d) ; off-sheet UART0_RX  [also labelled UART0_RX]
PWM2_M0/NPUAVS/UART0_TX/MCU_JTAG_TDI/GPIO0_C1_d: M5.20(PWM2_M0/NPUAVS/UART0_TX/MCU_JTAG_TDI/GPIO0_C1_d) ; off-sheet UART0_TX  [also labelled UART0_TX]
PWM3_IR/EDP_HPDIN_M1/PCIE30X1_WAKEn_M0/MCU_JTAG_TMS/GPIO0_C2_d: M5.21(PWM3_IR/EDP_HPDIN_M1/PCIE30X1_WAKEn_M0/MCU_JTAG_TMS/GPIO0_C2_d) ; off-sheet EDP_HPDIN_M1  [also labelled EDP_HPDIN_M1]
PWM7_IR: M5.25(PWM7_IR/SPI0_CS0_M0/PCIE30X2_PERSTn_M0/GPIO0_C6_d) ; off-sheet PWM7_IR  [also labelled PWM7_IR/SPI0_CS0_M0/PCIE30X2_PERSTn_M0/GPIO0_C6_d]
PWM12_M1/SPI3_MISO_M1/SATA1_ACT_LED/UART9_TX_M1/I2S3_SDO_M1/GPIO4_C5_d: M5.30(PWM12_M1/SPI3_MISO_M1/SATA1_ACT_LED/UART9_TX_M1/I2S3_SDO_M1/GPIO4_C5_d) ; off-sheet SPI3_MISO_M1  [also labelled SPI3_MISO_M1]
PWM13_M1/SPI3_CS0_M1/SATA0_ACT_LED/UART9_RX_M1/I2S3_SDI_M1/GPIO4_C6_d: M5.31(PWM13_M1/SPI3_CS0_M1/SATA0_ACT_LED/UART9_RX_M1/I2S3_SDI_M1/GPIO4_C6_d) ; off-sheet SPI3_CS0_M1  [also labelled SPI3_CS0_M1]
PWM14_M0/VOP_PWM_M1/GMAC1_MDC_M0/UART7_TX_M1/PDM_CLK1_M2/GPIO3_C4_d: M5.107(PWM14_M0/VOP_PWM_M1/GMAC1_MDC_M0/UART7_TX_M1/PDM_CLK1_M2/GPIO3_C4_d) ; off-sheet UART7_TX_M1  [also labelled UART7_TX_M1]
PWM14_M1/SPI3_CLK_M1/CAN1_RX_M1/PCIE30X2_CLKREQn_M2/I2S3_MCLK_M1/GPIO4_C2_d: M5.27(PWM14_M1/SPI3_CLK_M1/CAN1_RX_M1/PCIE30X2_CLKREQn_M2/I2S3_MCLK_M1/GPIO4_C2_d) ; off-sheet SPI3_CLK_M1  [also labelled SPI3_CLK_M1]
PWM15_IR_M0/SPDIF_TX_M1/GMAC1_MDIO_M0/UART7_RX_M1/I2S1_LRCK_RX_M2/GPIO3_C5_d: M5.106(PWM15_IR_M0/SPDIF_TX_M1/GMAC1_MDIO_M0/UART7_RX_M1/I2S1_LRCK_RX_M2/GPIO3_C5_d) ; off-sheet UART7_RX_M1  [also labelled UART7_RX_M1]
PWM15_IR_M1/SPI3_MOSI_M1/CAN1_TX_M1/PCIE30X2_WAKEn_M2/I2S3_SCLK_M1/GPIO4_C3_d: M5.28(PWM15_IR_M1/SPI3_MOSI_M1/CAN1_TX_M1/PCIE30X2_WAKEn_M2/I2S3_SCLK_M1/GPIO4_C3_d) ; off-sheet SPI3_MOSI_M1  [also labelled SPI3_MOSI_M1]
RK809_PWRON: M5.8(RK809_PWRON) ; off-sheet RK809_PWRON
RK809_VDC: M5.6(RK809_VDC) ; off-sheet RK809_VDC
SARADC_VIN0_KEY/RECOVERY: M5.15(SARADC_VIN0_KEY/RECOVERY) ; off-sheet SARADC_VIN0_KEY/RECOVERY
SARADC_VIN2_HP_HOOK: M5.16(SARADC_VIN2_HP_HOOK) ; off-sheet SARADC_VIN2_HP_HOOK
SARADC_VIN4: M5.17(SARADC_VIN4) ; off-sheet SARADC_VIN4
SARADC_VIN5: M5.18(SARADC_VIN5) ; off-sheet SARADC_VIN5
SDMMC0_CLK: M5.63(SDMMC0_CLK/TEST_CLKOUT/UART5_TX_M0/CAN0_RX_M1/GPIO2_A2_d) ; off-sheet SDMMC0_CLK  [also labelled SDMMC0_CLK/TEST_CLKOUT/UART5_TX_M0/CAN0_RX_M1/GPIO2_A2_d]
SDMMC0_CMD: M5.64(SDMMC0_CMD/PWM10_M1/UART5_RX_M0/CAN0_TX_M1/GPIO2_A1_u) ; off-sheet SDMMC0_CMD  [also labelled SDMMC0_CMD/PWM10_M1/UART5_RX_M0/CAN0_TX_M1/GPIO2_A1_u]
SDMMC0_D0: M5.68(SDMMC0_D0/UART2_TX_M1/UART6_TX_M1/PWM8_M1/GPIO1_D5_u) ; off-sheet SDMMC0_D0  [also labelled SDMMC0_D0/UART2_TX_M1/UART6_TX_M1/PWM8_M1/GPIO1_D5_u]
SDMMC0_D1: M5.67(SDMMC0_D1/UART2_RX_M1/UART6_RX_M1/PWM9_M1/GPIO1_D6_u) ; off-sheet SDMMC0_D1  [also labelled SDMMC0_D1/UART2_RX_M1/UART6_RX_M1/PWM9_M1/GPIO1_D6_u]
SDMMC0_D2: M5.66(SDMMC0_D2/ARMJTAG_TCK/UART5_CTSn_M0/GPIO1_D7_u) ; off-sheet SDMMC0_D2  [also labelled SDMMC0_D2/ARMJTAG_TCK/UART5_CTSn_M0/GPIO1_D7_u]
SDMMC0_D3: M5.65(SDMMC0_D3/ARMJTAG_TMS/UART5_RTSn_M0/GPIO2_A0_u) ; off-sheet SDMMC0_D3  [also labelled SDMMC0_D3/ARMJTAG_TMS/UART5_RTSn_M0/GPIO2_A0_u]
SDMMC0_DET/SATA_CP_DET/PCIE30X1_CLKREQn_M0/GPIO0_A4_u: M5.62(SDMMC0_DET/SATA_CP_DET/PCIE30X1_CLKREQn_M0/GPIO0_A4_u) ; off-sheet SDMMC0_DET_L  [also labelled SDMMC0_DET_L]
SDMMC0_PWREN/SATA_MP_SWITCH/PCIE20_CLKREQn_M0/GPIO0_A5_d: M5.61(SDMMC0_PWREN/SATA_MP_SWITCH/PCIE20_CLKREQn_M0/GPIO0_A5_d) ; off-sheet USB_OTG_PWREN_H  [also labelled USB_OTG_PWREN_H]
SDMMC1_DET/I2C4_SCL_M1/UART8_CTSn_M0/CAN2_TX_M1/GPIO2_B2_u: M5.46(SDMMC1_DET/I2C4_SCL_M1/UART8_CTSn_M0/CAN2_TX_M1/GPIO2_B2_u) ; off-sheet UART8_CTSn_M0  [also labelled UART8_CTSn_M0]
SDMMC1_PWREN/I2C4_SDA_M1/UART8_RTSn_M0/CAN2_RX_M1/GPIO2_B1_d: M5.45(SDMMC1_PWREN/I2C4_SDA_M1/UART8_RTSn_M0/CAN2_RX_M1/GPIO2_B1_d) ; off-sheet UART8_RTSn_M0  [also labelled UART8_RTSn_M0]
UART2_RX_M0: M5.60(UART2_RX_M0/GPIO0_D0_u) ; off-sheet UART2_RX_M0  [also labelled UART2_RX_M0/GPIO0_D0_u]
UART2_TX_M0: M5.59(UART2_TX_M0/GPIO0_D1_u) ; off-sheet UART2_TX_M0  [also labelled UART2_TX_M0/GPIO0_D1_u]
USB2_HOST2_DM: M5.99(USB2_HOST2_DM) ; off-sheet USB2_HOST2_DM
USB2_HOST2_DP: M5.100(USB2_HOST2_DP) ; off-sheet USB2_HOST2_DP
USB2_HOST3_DM: M5.101(USB2_HOST3_DM) ; off-sheet USB2_HOST3_DM
USB2_HOST3_DP: M5.102(USB2_HOST3_DP) ; off-sheet USB2_HOST3_DP
USB3_HOST1_DM: M5.182(USB3_HOST1_DM) ; off-sheet USB3_HOST1_DM
USB3_HOST1_DP: M5.183(USB3_HOST1_DP) ; off-sheet USB3_HOST1_DP
USB3_HOST1_SSRXN: M5.185(USB3_HOST1_SSRXN/SATA1_RXN/QSGMII_RXN_M0) ; off-sheet USB3_HOST1_SSRXN  [also labelled USB3_HOST1_SSRXN/SATA1_RXN/QSGMII_RXN_M0]
USB3_HOST1_SSRXP: M5.184(USB3_HOST1_SSRXP/SATA1_RXP/QSGMII_RXP_M0) ; off-sheet USB3_HOST1_SSRXP  [also labelled USB3_HOST1_SSRXP/SATA1_RXP/QSGMII_RXP_M0]
USB3_HOST1_SSTXN: M5.181(USB3_HOST1_SSTXN/SATA1_TXN/QSGMII_TXN_M0) ; off-sheet USB3_HOST1_SSTXN  [also labelled USB3_HOST1_SSTXN/SATA1_TXN/QSGMII_TXN_M0]
USB3_HOST1_SSTXP: M5.180(USB3_HOST1_SSTXP/SATA1_TXP/QSGMII_TXP_M0) ; off-sheet USB3_HOST1_SSTXP  [also labelled USB3_HOST1_SSTXP/SATA1_TXP/QSGMII_TXP_M0]
USB3_OTG0_DM: M5.188(USB3_OTG0_DM) ; off-sheet USB3_OTG0_DM
USB3_OTG0_DP: M5.189(USB3_OTG0_DP) ; off-sheet USB3_OTG0_DP
USB3_OTG0_ID: M5.193(USB3_OTG0_ID) ; off-sheet USB3_OTG0_ID
USB3_OTG0_SSRXN: M5.191(USB3_OTG0_SSRXN/SATA0_RXN) ; off-sheet USB3_OTG0_SSRXN  [also labelled USB3_OTG0_SSRXN/SATA0_RXN]
USB3_OTG0_SSRXP: M5.190(USB3_OTG0_SSRXP/SATA0_RXP) ; off-sheet USB3_OTG0_SSRXP  [also labelled USB3_OTG0_SSRXP/SATA0_RXP]
USB3_OTG0_SSTXN: M5.187(USB3_OTG0_SSTXN/SATA0_TXN) ; off-sheet USB3_OTG0_SSTXN  [also labelled USB3_OTG0_SSTXN/SATA0_TXN]
USB3_OTG0_SSTXP: M5.186(USB3_OTG0_SSTXP/SATA0_TXP) ; off-sheet USB3_OTG0_SSTXP  [also labelled USB3_OTG0_SSTXP/SATA0_TXP]
USB3_OTG0_VBUSDET: M5.192(USB3_OTG0_VBUSDET) ; off-sheet USB3_OTG0_VBUSDET

Not connected (* = marked no-connect by the designer): M5 205(SNSN) 206(SNSP) 207(BATDIV)

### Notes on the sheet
- HDMI2.0_TX
- MIPI_RX
- MicroSD Card
- MIPI_DSI_TX0
- PCIE2.0
- Debug UART2
- MIPI_DSI_TX1
- RK809-5
- USB3.0
- eDP_TX
- ADC
- USB2.0
- VCCIO4_1.8V_3.3V
- Default 1.8V
- VCCIO5_3.3V
- Default 3.3V
- VCCIO6_1.8V_3.3V
- PMUIO1/2_3.3V
- VCCIO1_3.3V
- VCCIO7_3.3V

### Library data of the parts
C30-C33 = C-0603: Part Number: C020102120071; Part Name: 贴片电容; Manufacture: 三星¦国巨¦村田; PCB Footprint: C0603L; ERP Number: 1010200076; DSC1: ±20%; DSC3: X5R; ID: 71
M5 = MODE-204P_2

## Sheet P06.SchDoc
size 297 x 209 mm
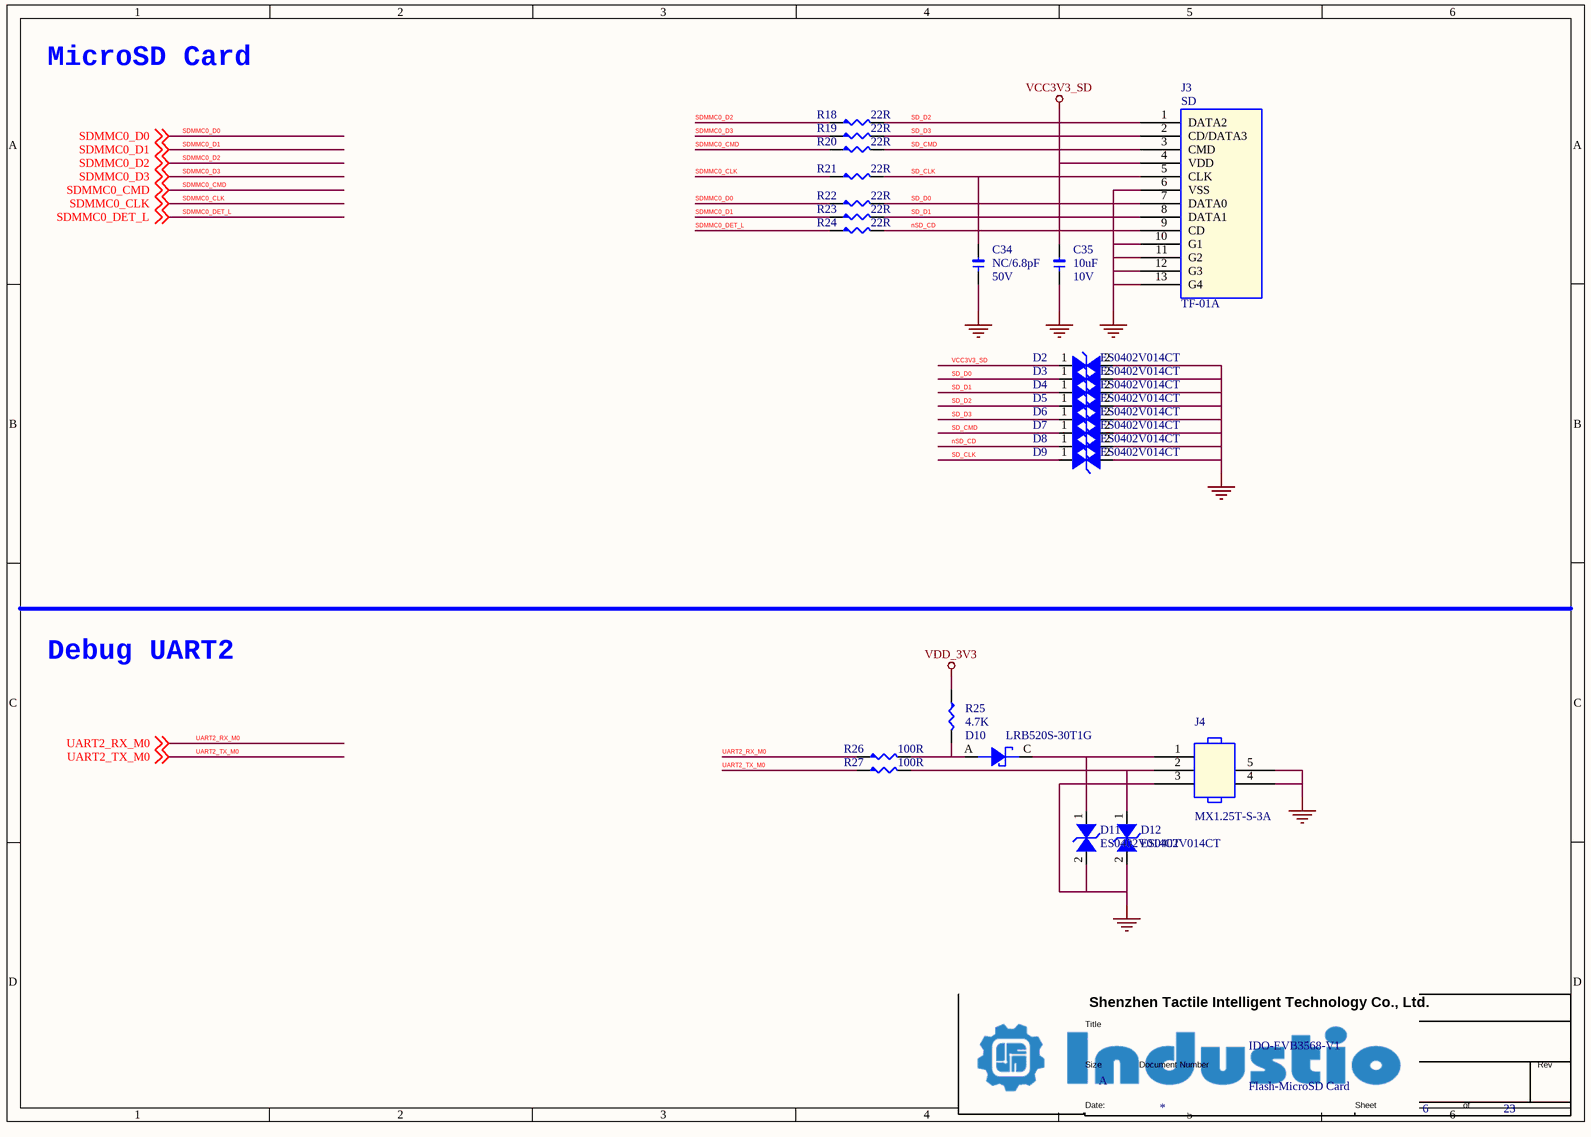
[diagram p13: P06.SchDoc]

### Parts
(Parts that share a designator on the sheet are numbered #1, #2 ... from top to bottom, then left to right.)
*#6  Doc: Flash-MicroSD Card  Title: IDO-EVB3568-V1  Page Size: A  Page Number: 6  Page Count: 23  (hidden comment: TitleBlock1)  (graphical)
C34  NC/6.8pF  DSC2: 50V  [1206]
C35  10uF  DSC2: 10V  [1206]
D2  ES0402V014CT  [V0402]
D3  ES0402V014CT  [V0402]
D4  ES0402V014CT  [V0402]
D5  ES0402V014CT  [V0402]
D6  ES0402V014CT  [V0402]
D7  ES0402V014CT  [V0402]
D8  ES0402V014CT  [V0402]
D9  ES0402V014CT  [V0402]
D10  LRB520S-30T1G  [SOD523]
D11  ES0402V014CT  [V0402]
D12  ES0402V014CT  [V0402]
J3  SD  [TF-01A]
J4  MX1.25T-S-3A  [MX125T-S-3A]
R18  22R  [R0402L]
R19  22R  [R0402L]
R20  22R  [R0402L]
R21  22R  [R0402L]
R22  22R  [R0402L]
R23  22R  [R0402L]
R24  22R  [R0402L]
R25  4.7K  [R0402L]
R26  100R  [R0402L]
R27  100R  [R0402L]

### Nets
GND: C34.1 C35.1 D2.2(I/O1) D3.2(I/O1) D4.2(I/O1) D5.2(I/O1) D6.2(I/O1) D7.2(I/O1) D8.2(I/O1) D9.2(I/O1) D11.2(I/O1) D12.2(I/O1) J3.6(VSS) J3.10(G1) J3.11(G2) J3.12(G3) J3.13(G4) J4.3 J4.4 J4.5
VCC3V3_SD: C35.2 D2.1(I/O2) J3.4(VDD)
VDD_3V3: R25.1
nSD_CD: D8.1(I/O2) J3.9(CD) R24.2
SD_CLK: C34.2 D9.1(I/O2) J3.5(CLK) R21.2
SD_CMD: D7.1(I/O2) J3.3(CMD) R20.2
SD_D0: D3.1(I/O2) J3.7(DATA0) R22.2
SD_D1: D4.1(I/O2) J3.8(DATA1) R23.2
SD_D2: D5.1(I/O2) J3.1(DATA2) R18.2
SD_D3: D6.1(I/O2) J3.2(CD/DATA3) R19.2
SDMMC0_CLK: R21.1 ; off-sheet SDMMC0_CLK
SDMMC0_CMD: R20.1 ; off-sheet SDMMC0_CMD
SDMMC0_D0: R22.1 ; off-sheet SDMMC0_D0
SDMMC0_D1: R23.1 ; off-sheet SDMMC0_D1
SDMMC0_D2: R18.1 ; off-sheet SDMMC0_D2
SDMMC0_D3: R19.1 ; off-sheet SDMMC0_D3
SDMMC0_DET_L: R24.1 ; off-sheet SDMMC0_DET_L  [project net SDMMC0_DET/SATA_CP_DET/PCIE30X1_CLKREQn_M0/GPIO0_A4_u]
UART2_RX_M0: R26.1 ; off-sheet UART2_RX_M0
UART2_TX_M0: R27.1 ; off-sheet UART2_TX_M0
NetD10_A: D10.A R25.2 R26.2
NetD10_C: D10.C D11.1(I/O2) J4.1
NetD12_1: D12.1(I/O2) J4.2 R27.2

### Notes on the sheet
- MicroSD Card
- Debug UART2

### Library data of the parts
C34 = C-0402_Dup1: Part Number: C020102120018; Part Name: 贴片电容; Manufacture: 三星¦国巨¦村田; PCB Footprint: C0402L; ERP Number: 1010200056; DSC1: ±0.25PF; DSC3: C0G; ID: 18
C35 = C-0603: Manufacture: 三星¦国巨¦村田; Part Name: 贴片电容; Part Number: C020102120071; PCB Footprint: C0603L; ID: 71; DSC3: X5R; DSC1: ±20%; ERP Number: 1010200076
D2-D7 D11 D12 = DI-ESD: ESD 0402; Part Number: C040502250002; Manufacture P/N: MLVG04021R0UV18; Manufacturer: INPAQ; Manufacture: AEM; PN Type: Varistor; ERP Number: 1010800023; DSC1: 双向; DSC2: Vdc=14V; DSC3: Vbr=300V; DSC4: Vc=30V; DSC5: Cj=0.25pF; ID: 2
D8 D9 = DI-ESD: ESD 0402; Part Number: C040502250002; Manufacture P/N: MLVG04021R0UV18; Manufacturer: INPAQ; Manufacture: AEM; PN Type: Varistor; ID: 2; DSC5: Cj=0.25pF; DSC4: Vc=30V; DSC3: Vbr=300V; DSC2: Vdc=14V; DSC1: 双向; ERP Number: 1010800023
D10 = DI-XI-S: Manufacture: 乐山无线电; Part Name: 肖特基二级管; Part Number: C040202220002; CLASS: IC; Solder: 推荐; ID: 2; DSC4: IR=0.5uA; DSC3: VF=350mV/10mA; DSC2: IF=200mA; DSC1: VR=30V
J3 = J-TF-01A: Part Name: SD卡座; Part Number: J080102980002; ID: 2; DSC4: TF-01A(韩荣); DSC3: 贴片; DSC1: TF卡座 自弹式
J4 = J-A-3P: Part Number: J020102800059; ID: 7; DSC5: A1251WV-S-3P(CJT); DSC4: 米黄色胶壳 耐高温; DSC3: 立贴; DSC2: 1.25mm间距; DSC1: 3p
R18-R22 R24 = R-0402_Dup1: Part Name: 贴片电阻; Part Number: C011002080552; DSC1: ±1%; DSC2: 1/16W; ID: 552
R23 = R-0402_Dup1: Part Number: C011002080552; Part Name: 贴片电阻; ID: 552; DSC2: 1/16W; DSC1: ±1%
R25 = R-0402_Dup1: Part Name: 贴片电阻; Part Number: C011002080818; ERP Number: 1010200445; DSC1: ±1%; DSC2: 1/16W; ID: 818
R26 R27 = R-0402_Dup1: Part Name: 贴片电阻; Part Number: C011002080630; ERP Number: 1010200450; DSC1: ±1%; DSC2: 1/16W; ID: 630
